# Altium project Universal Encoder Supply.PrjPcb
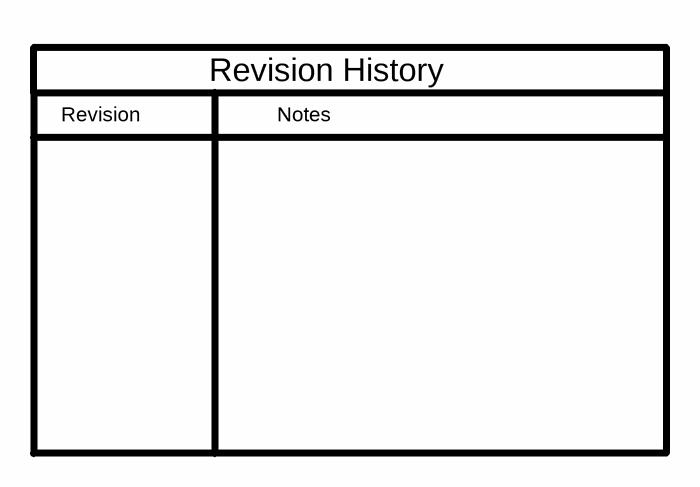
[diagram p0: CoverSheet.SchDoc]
CopyrightYear: 2015; EVM_Orderable: N/A; PCB_Layout: V.Pizzolante; PCB_Rev: E1; PRJ_Customer: Public Release; PRJ_Engineer: V.Pizzolante; PRJ_Number: TIDA-00179; PRJ_Title: Universal Digital Interface to Absolute Encoders; SCH_Rev: E1; TechSupport: http://www.ti.com/support; TID: TIDA-00179
6 sheets, 194 parts. Net scope: global (net labels, ports and power ports of the same name join across sheets).
Board file: TID.PcbDoc
Sheets:
  CoverSheet.SchDoc
  Power.SchDoc
  Protections.SchDoc
  Host_Interface_MUX.SchDoc
  RS485.SchDoc
  TID_Hardware.SchDoc

## Sheet CoverSheet.SchDoc
size 431 x 279 mm; Date: Not shown in title block; ApprovedBy: Not shown in title block; CheckedBy: Not shown in title block; Author: Not shown in title block; CompanyName: Not shown in title block; Engineer: Not shown in title block; Organization: Not shown in title block; Address1: Not shown in title block; Address2: Not shown in title block; Address3: Not shown in title block; Address4: Not shown in title block; DocumentNumber: 1; Revision: Use project parameter SCH_Rev; SheetNumber: 1; SheetTotal: 3; PageSetup: Record=PageOptions¦CenterHorizontal=True¦CenterVertical=True¦PrintScale=0.64¦XCorrection=1.00¦YCorrection=1.00¦PrintKind=0¦BorderSize=5000000¦LeftOffset=0¦BottomOffset=0¦Orientation=2¦PaperLength=1000¦PaperWidth=1000¦Scale=100¦PaperSource=15¦PrintQuality=600¦MediaType=1¦DitherType=10¦PrintScaleMode=1¦PaperKind=Letter

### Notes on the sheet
- Revision
- Notes
- Revision History

## Sheet Power.SchDoc
size 431 x 279 mm; Date: Not shown in title block; ApprovedBy: Not shown in title block; CheckedBy: Not shown in title block; Author: Not shown in title block; CompanyName: Not shown in title block; Engineer: Not shown in title block; Organization: Not shown in title block; Address1: Not shown in title block; Address2: Not shown in title block; Address3: Not shown in title block; Address4: Not shown in title block; DocumentNumber: 1; Revision: Use project parameter SCH_Rev; SheetNumber: 2; SheetTotal: 3
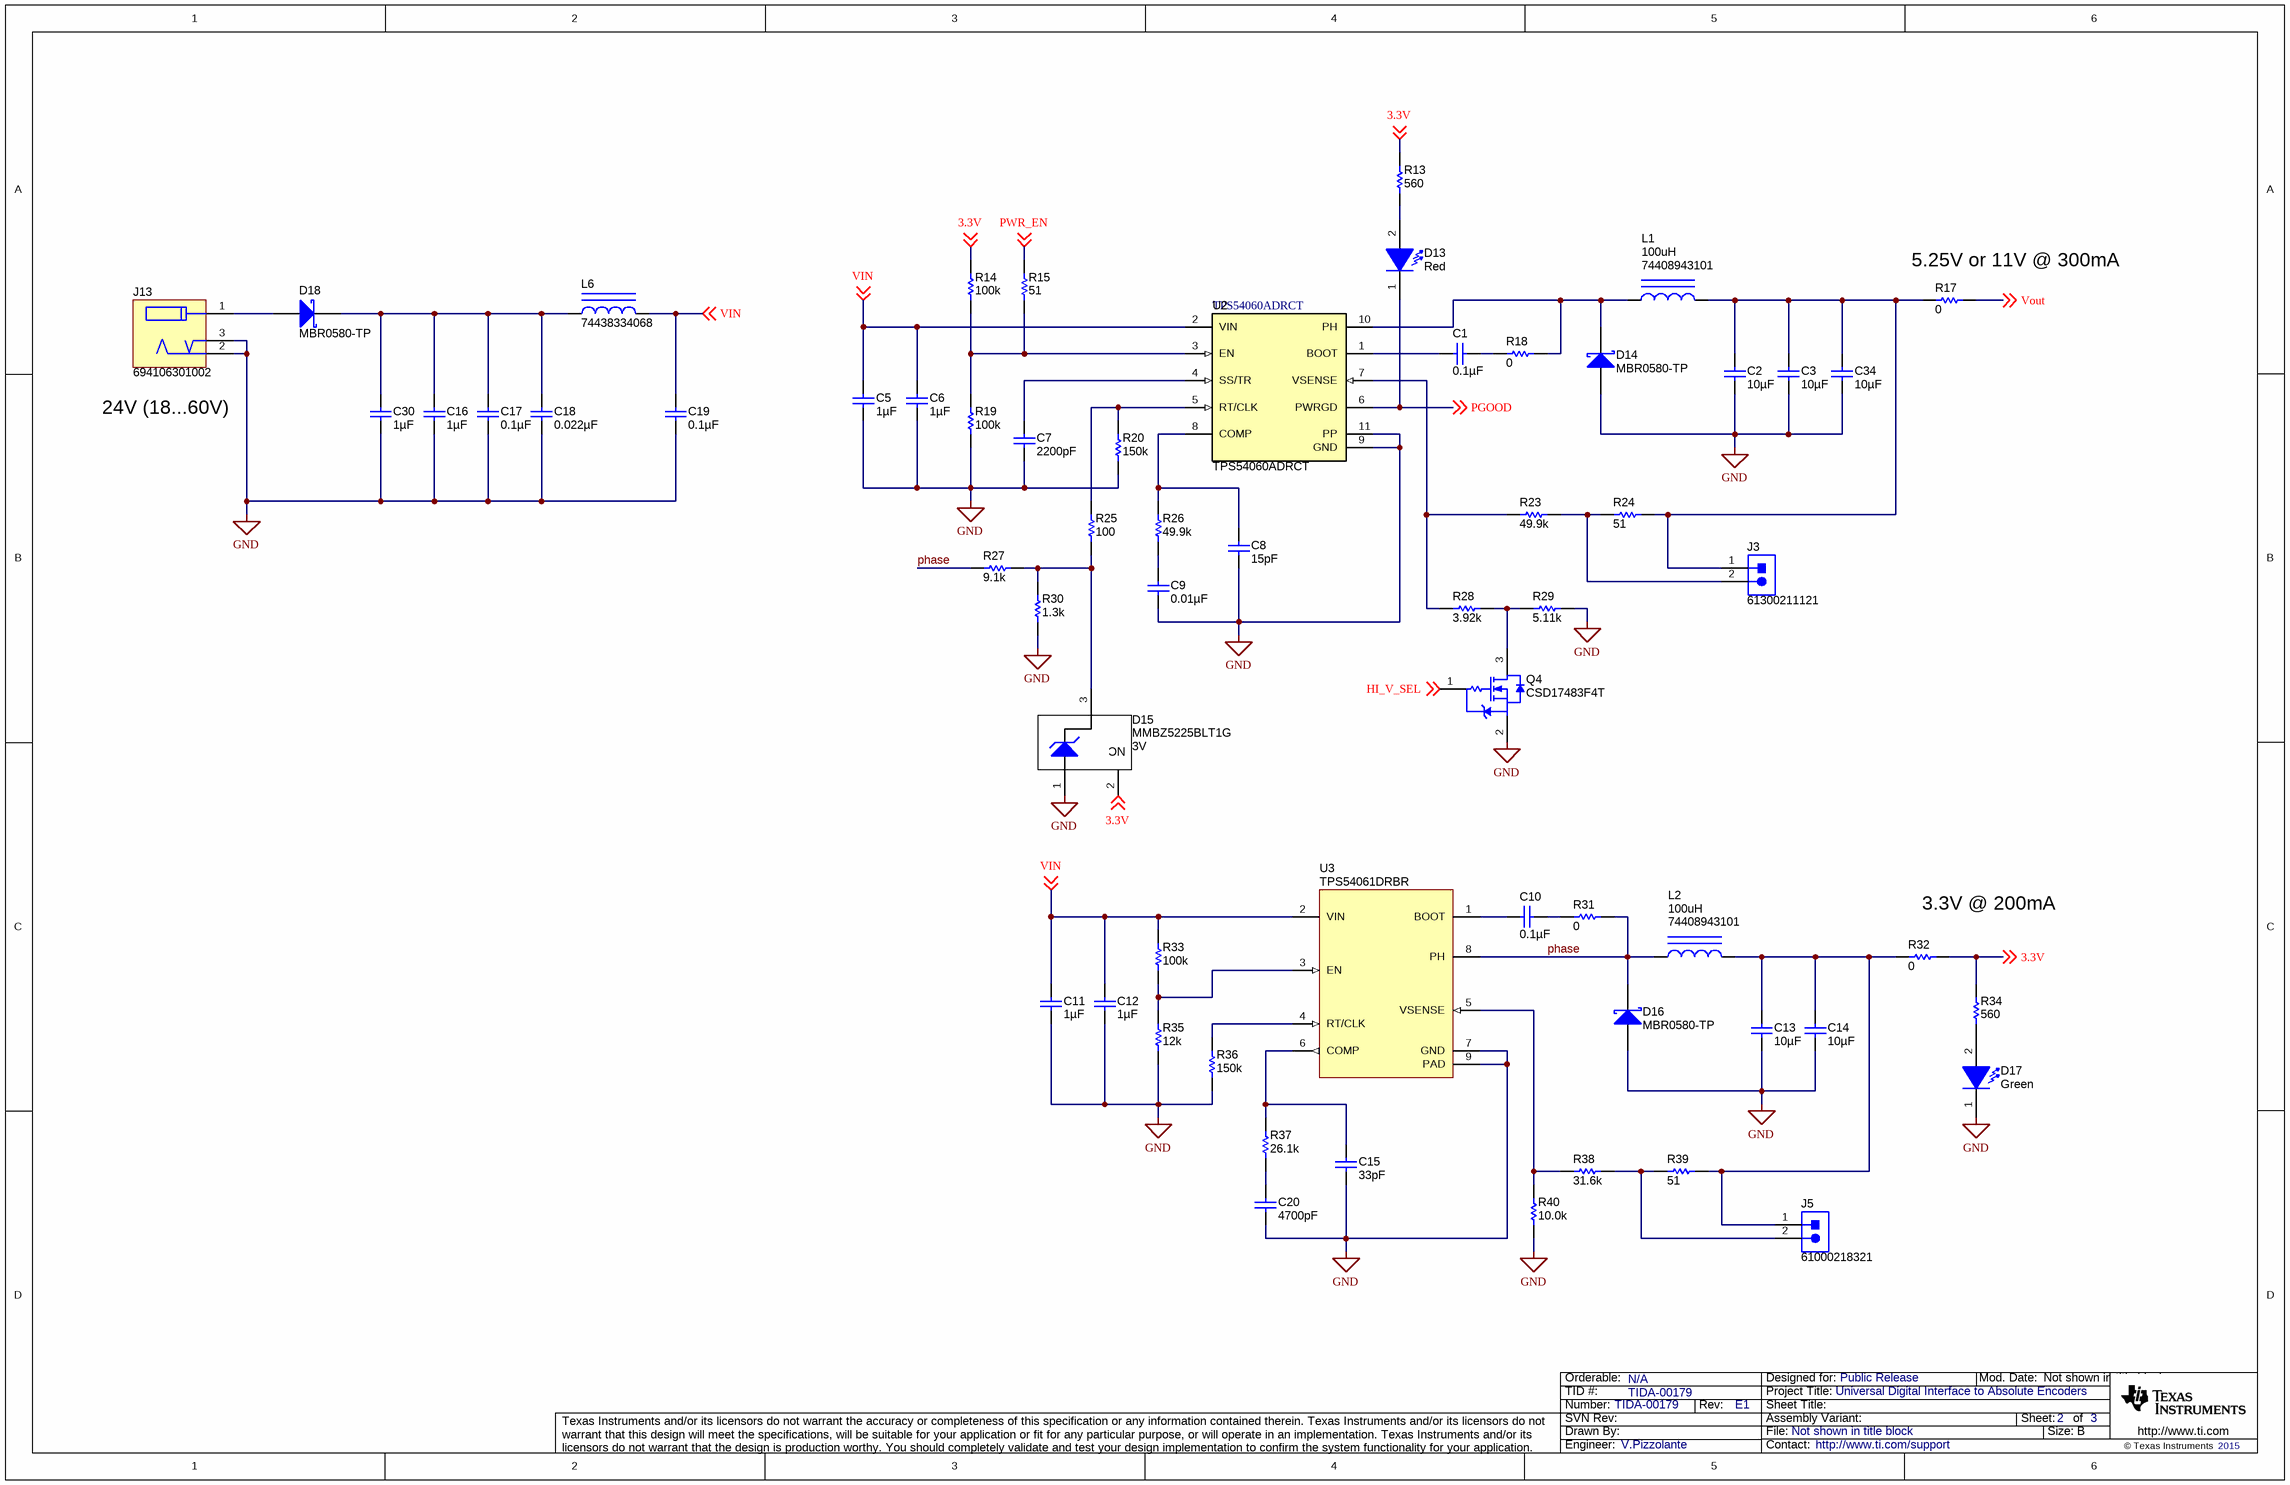
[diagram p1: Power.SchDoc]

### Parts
C1  ValueDisplayed: 0.1µF  [0603]  (hidden comment: GRM188R72A104KA35D)
C2  ValueDisplayed: 10µF  [0805_HV]  (hidden comment: C2012X5R1E106K125AB)
C3  ValueDisplayed: 10µF  [0805_HV]  (hidden comment: C2012X5R1E106K125AB)
C5  ValueDisplayed: 1µF  [0805_145]  (hidden comment: C2012X7S2A105K125AB)
C6  ValueDisplayed: 1µF  [0805_145]  (hidden comment: C2012X7S2A105K125AB)
C7  ValueDisplayed: 2200pF  [0603_095]  (hidden comment: 885012206036)
C8  ValueDisplayed: 15pF  [0402]  (hidden comment: 885012005056)
C9  ValueDisplayed: 0.01µF  [0402]  (hidden comment: 885012205031)
C10  ValueDisplayed: 0.1µF  [0603]  (hidden comment: GRM188R72A104KA35D)
C11  ValueDisplayed: 1µF  [0805_145]  (hidden comment: C2012X7S2A105K125AB)
C12  ValueDisplayed: 1µF  [0805_145]  (hidden comment: C2012X7S2A105K125AB)
C13  ValueDisplayed: 10µF  [0805_HV]  (hidden comment: C2012X5R1E106K125AB)
C14  ValueDisplayed: 10µF  [0805_HV]  (hidden comment: C2012X5R1E106K125AB)
C15  ValueDisplayed: 33pF  [0402]  (hidden comment: 885012005043)
C16  ValueDisplayed: 1µF  [0805_145]  (hidden comment: C2012X7S2A105K125AB)
C17  ValueDisplayed: 0.1µF  [0805_HV]  (hidden comment: C0805C104K1RACTU)
C18  ValueDisplayed: 0.022µF  [0603]  (hidden comment: C1608X7R2A223K)
C19  ValueDisplayed: 0.1µF  [0805_HV]  (hidden comment: C0805C104K1RACTU)
C20  ValueDisplayed: 4700pF  [0402]  (hidden comment: GRM155R71E472KA01D)
C30  ValueDisplayed: 1µF  [0805_145]  (hidden comment: C2012X7S2A105K125AB)
C34  ValueDisplayed: 10µF  [0805_HV]  (hidden comment: C2012X5R1E106K125AB)
D13  value Red  [WL-SMCW_RED]  (hidden comment: 150060RS75000)
D14  MBR0580-TP  [SOD-123]
D15  MMBZ5225BLT1G  value 3V  [SOT-23]
D16  MBR0580-TP  [SOD-123]
D17  value Green  [WL-SMCW_GREEN]  (hidden comment: 150060GS75000)
D18  MBR0580-TP  [SOD-123]
J3  61300211121  [WURTH_61300211121]
J5  61000218321  [Wurth_61000218321]
J13  694106301002  [Wurth_694106301002]
L1  74408943101  value 100uH  [WE-SPC_4838]
L2  74408943101  value 100uH  [WE-SPC_4838]
L6  74438334068  [WE-MAPI_3012]
Q4  CSD17483F4T  [YJC0003A]
R13  ValueDisplayed: 560  [0402]  (hidden comment: CRCW0402560RJNED)
R14  ValueDisplayed: 100k  [0402]  (hidden comment: CRCW0402100KJNED)
R15  ValueDisplayed: 51  [0402]  (hidden comment: CRCW040251R0JNED)
R17  value 0  [0603]  (hidden comment: CRCW06030000Z0EA)
R18  ValueDisplayed: 0  [0402]  (hidden comment: CRCW04020000Z0ED)
R19  ValueDisplayed: 100k  [0402]  (hidden comment: CRCW0402100KJNED)
R20  ValueDisplayed: 150k  [0402]  (hidden comment: CRCW0402150KJNED)
R23  ValueDisplayed: 49.9k  [0402]  (hidden comment: CRCW040249K9FKED)
R24  ValueDisplayed: 51  [0402]  (hidden comment: CRCW040251R0JNED)
R25  ValueDisplayed: 100  [0402]  (hidden comment: CRCW0402100RJNED)
R26  ValueDisplayed: 49.9k  [0402]  (hidden comment: CRCW040249K9FKED)
R27  ValueDisplayed: 9.1k  [0402]  (hidden comment: CRCW04029K10JNED)
R28  ValueDisplayed: 3.92k  [0402]  (hidden comment: CRCW04023K92FKED)
R29  ValueDisplayed: 5.11k  [0402]  (hidden comment: CRCW04025K11FKED)
R30  ValueDisplayed: 1.3k  [0402]  (hidden comment: CRCW04021K30JNED)
R31  ValueDisplayed: 0  [0402]  (hidden comment: CRCW04020000Z0ED)
R32  value 0  [0603]  (hidden comment: CRCW06030000Z0EA)
R33  ValueDisplayed: 100k  [0402]  (hidden comment: CRCW0402100KJNED)
R34  ValueDisplayed: 560  [0402]  (hidden comment: CRCW0402560RJNED)
R35  ValueDisplayed: 12k  [0402]  (hidden comment: CRCW040212K0JNED)
R36  ValueDisplayed: 150k  [0402]  (hidden comment: CRCW0402150KJNED)
R37  ValueDisplayed: 26.1k  [0402]  (hidden comment: CRCW040226K1FKED)
R38  ValueDisplayed: 31.6k  [0402]  (hidden comment: CRCW040231K6FKED)
R39  ValueDisplayed: 51  [0402]  (hidden comment: CRCW040251R0JNED)
R40  ValueDisplayed: 10.0k  [0402]  (hidden comment: CRCW040210K0FKED)
U2  TPS54060ADRCT  [DRC0010J]
U3  TPS54061DRBR  [DRB0008B]

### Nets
GND: C2.2 C3.2 C5.2 C6.2 C7.2 C8.2 C9.2 C11.2 C12.2 C13.2 C14.2 C15.2 C16.2 C17.2 C18.2 C19.2 C20.2 C30.2 C34.2 D14.2(A) D15.1(A) D16.2(A) D17.1(K) J13.2 J13.3 Q4.2(S) R19.1 R20.1 R29.2 R30.1 R35.1 R36.1 R40.1 U2.9(GND) U2.11(PP) U3.7(GND) U3.9(PAD)
3.3V: D15.2(NC) R13.2 R14.2 R32.2 R34.2 ; off-sheet 3.3V
HI_V_SEL: Q4.1(G) ; off-sheet HI_V_SEL
PGOOD: D13.1(K) U2.6(PWRGD) ; off-sheet PGOOD
phase: D16.1(K) L2.1 R27.1 R31.2 U3.8(PH)
PWR_EN: R15.2 ; off-sheet PWR_EN
VIN: C5.1 C6.1 C11.1 C12.1 C19.1 L6.2 R33.1 U2.2(VIN) U3.2(VIN) ; off-sheet VIN
Vout: R17.2 ; off-sheet Vout
NetC1_1: C1.1 R18.1
NetC1_2: C1.2 U2.1(BOOT)
NetC2_1: C2.1 C3.1 C34.1 J3.1 L1.2 R17.1 R24.2
NetC7_1: C7.1 U2.4(SS/TR)
NetC8_1: C8.1 R26.2 U2.8(COMP)
NetC9_1: C9.1 R26.1
NetC10_1: C10.1 R31.1
NetC10_2: C10.2 U3.1(BOOT)
NetC13_1: C13.1 C14.1 J5.1 L2.2 R32.1 R39.2
NetC15_1: C15.1 R37.2 U3.6(COMP)
NetC16_1: C16.1 C17.1 C18.1 C30.1 D18.1(K) L6.1
NetC20_1: C20.1 R37.1
NetD13_2: D13.2(A) R13.1
NetD14_1: D14.1(K) L1.1 R18.2 U2.10(PH)
NetD15_3: D15.3(K) R25.1 R27.2 R30.2
NetD17_2: D17.2(A) R34.1
NetD18_2: D18.2(A) J13.1
NetJ3_2: J3.2 R23.1 R24.1
NetJ5_2: J5.2 R38.2 R39.1
NetQ4_3: Q4.3(D) R28.2 R29.1
NetR14_1: R14.1 R15.1 R19.2 U2.3(EN)
NetR20_2: R20.2 R25.2 U2.5(RT/CLK)
NetR23_2: R23.2 R28.1 U2.7(VSENSE)
NetR33_2: R33.2 R35.2 U3.3(EN)
NetR36_2: R36.2 U3.4(RT/CLK)
NetR38_1: R38.1 R40.2 U3.5(VSENSE)

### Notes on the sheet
- (near R17) 5.25V or 11V @ 300mA
- (near J13) 24V (18...60V)
- (near R32) 3.3V @ 200mA

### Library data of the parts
C1 C10 = GRM188R72A104KA35D: CAP, CERM, 0.1 µF, 100 V, +/- 10%, X7R, 0603; Manufacturer: MuRata; Polarized: N; CompType: Capacitor; Value: 0.1uF; U/M: EA; Cap_F: 0.0000001; Tolerance_%: 10; Value1: Unknown; VDC_V: 100; Value2: 100V; TaMin_C: -55; TaMax_C: 125
C2 C3 C13 C14 C34 = C2012X5R1E106K125AB: CAP, CERM, 10uF, 25V, +/-10%, X5R, 0805; Manufacturer: TDK; Polarized: N; CompType: Capacitor; U/M: EA; Cap_F: 0.00001; Tolerance_%: 10; Value1: Unknown; VDC_V: 25; TaMin_C: -55; TaMax_C: 85; Cap_Case: 0805
C5 C6 C11 C12 C16 C30 = C2012X7S2A105K125AB: CAP, CERM, 1 µF, 100 V, +/- 10%, X7S, 0805; Manufacturer: TDK; Polarized: N; CompType: Capacitor; Value: 1uF; U/M: EA; Cap_F: 0.000001; Tolerance_%: 10; Value1: Unknown; VDC_V: 100; Value2: 100V; TaMin_C: -55; TaMax_C: 125; Cap_Case: 0805
C7 = 885012206036: CAP, CERM, 2200 pF, 16 V, +/- 10%, X7R, 0603_095; Manufacturer: Wurth Elektronik; Polarized: N; CompType: Capacitor; Value: 2200pF; U/M: EA; Cap_F: 0.0000000022; Tolerance_%: 10; Value1: Unknown; VDC_V: 16; Value2: 16V; TaMin_C: -55; TaMax_C: 125; Cap_Case: 0603
C8 = 885012005056: CAP, CERM, 15 pF, 50 V, +/- 5%, C0G/NP0, 0402; Manufacturer: Wurth Elektronik; Polarized: N; CompType: Capacitor; Value: 15pF; U/M: EA; Cap_F: 0.000000000015; Tolerance_%: 5; Value1: Unknown; VDC_V: 50; Value2: 50V; TaMin_C: -55; TaMax_C: 125
C9 = 885012205031: CAP, CERM, 0.01 µF, 16 V, +/- 10%, X7R, 0402; Manufacturer: Wurth Elektronik; Polarized: N; CompType: Capacitor; Value: 0.01uF; U/M: EA; Cap_F: 0.00000001; Tolerance_%: 10; Value1: Unknown; VDC_V: 16; Value2: 16V; TaMin_C: -55; TaMax_C: 125
C15 = 885012005043: CAP, CERM, 33 pF, 25 V, +/- 5%, C0G/NP0, 0402; Manufacturer: Wurth Elektronik; Polarized: N; CompType: Capacitor; Value: 33pF; U/M: EA; Cap_F: 0.000000000033; Tolerance_%: 5; Value1: Unknown; VDC_V: 25; Value2: 25V; TaMin_C: -55; TaMax_C: 125
C17 C19 = C0805C104K1RACTU: CAP, CERM, 0.1 µF, 100 V, +/- 10%, X7R, 0805; Manufacturer: Kemet; Polarized: N; CompType: Capacitor; Value: 0.1uF; U/M: EA; Cap_F: 0.0000001; Tolerance_%: 10; ESR_ohm: 0.064; Value1: 0.064 ohm; VDC_V: 100; Value2: 100V; IRMS_A: 1.64; TaMin_C: -55; TaMax_C: 125; Cap_Case: 0805
C18 = C1608X7R2A223K: CAP, CERM, 0.022 µF, 100 V, +/- 10%, X7R, 0603; Manufacturer: TDK; Polarized: N; CompType: Capacitor; Value: 0.022uF; U/M: EA; Cap_F: 0.000000022; Tolerance_%: 10; ESR_ohm: 0.037; Value1: 0.037 ohm; VDC_V: 100; Value2: 100V; TaMin_C: -55; TaMax_C: 125
C20 = GRM155R71E472KA01D: CAP, CERM, 4700 pF, 25 V, +/- 10%, X7R, 0402; Manufacturer: MuRata; Polarized: N; CompType: Capacitor; Value: 4700pF; U/M: EA; Cap_F: 0.0000000047; Tolerance_%: 10; Value1: Unknown; VDC_V: 25; Value2: 25V; TaMin_C: -55; TaMax_C: 125
D13 = 150060RS75000: LED, Red, SMD; Manufacturer: Wurth Elektronik; Type: AlInGaP; Vf_V: 2; Value2: 2V; Io_A: 0.03; Vr_V: 5; Tjmax_C: 85; Power_TotalModule: 0.072; Value1: 0.072W; Angle: 140; U/M: EA
D14 D16 D18 = MBR0580-TP: Diode, Schottky, 80 V, 0.5 A, SOD-123; Manufacturer: Micro Commercial Components; U/M: EA; Vf_V: 0.8; Value: 80V; Value1: 0.5A; Value2: 0.8V; Io_A: 0.5; Vr_V: 80; TJmax_C: 150
D15 = MMBZ5225BLT1G: Diode, Zener, 3 V, 225 mW, SOT-23; Manufacturer: ON Semiconductor; U/M: EA; Power_W: 0.225; Vz_V: 3; Value1: 0.225W; RJA_CperW: 556
D17 = 150060GS75000: LED, Green, SMD; Manufacturer: Wurth Elektronik; Type: InGaN; Vf_V: 3.2; Value2: 3.2V; Io_A: 0.02; Tjmax_C: 85; Value1: W; Angle: 140; U/M: EA
J3 = 61300211121: Header, 2.54 mm, 2x1, Gold, TH; Manufacturer: Wurth Elektronik; SymbolCreator: a0412235; U/M: EA
J5 = 61000218321: Header, 2.54mm, 2x1, Gold, SMT; Manufacturer: Wurth Elektronik; SymbolCreator: a0412235; U/M: EA
J13 = 694106301002: WR-DC DC Power Jack, R/A, TH; Manufacturer: Wurth Elektronik; SymbolCreator: a0799628; U/M: EA
L1 L2 = 74408943101: Inductor, Shielded Drum Core, Ferrite, 100 µH, 0.52 A, 0.77 ohm, SMD; Manufacturer: Wurth Elektronik; Ind_H: 100.0E-6; ValueDisplayed: 100µH; Imax_A: 0.52; Irms: 0.52A @ 40C rise; Isat: 0.68A @ 35% inductance drop; DCR_ohm: 0.77; Value2: 0.52A
L6 = 74438334068: Inductor, Shielded, 6.8 µH, 0.88 A, 0.3682 ohm, SMD; Manufacturer: Wurth Elektronik; Value: 6.8uH; Ind_H: 6.8E-6; ValueDisplayed: 6.8µH; Imax_A: 0.88; Irms: 0.88A @ 40C rise; Isat: 2.7A @ 20% inductance drop; DCR_ohm: 0.3682; Value2: 0.88A
Q4 = CSD17483F4T: MOSFET, N/P-CH, 30 V, 1.5 A,; Manufacturer: Texas Instruments; Alternate Manufacturer: None; U/M: EA; ChType: N; Value: 30V; VdsMax_V: 30; Value1: 0.2 ohm; Rdson45_ohm: 0.2; Value2: 1.01 nC; QgTyp_nC: 1.01; Vgs_V: 12; IdsMax_A: 1.5; SymbolCreator: a0411947
R13 R34 = CRCW0402560RJNED: RES, 560, 5%, 0.063 W, 0402; Manufacturer: Vishay-Dale; CompType: Resistor; Value: 560; Value_Code: 560R; Tolerance_%: 5; Power_W: 0.063; Value2: 0.063W; VDC_V: 50; TempCo: 200 ppm/C; EIA_Code: E24; U/M: EA
R14 R19 R33 = CRCW0402100KJNED: RES, 100 k, 5%, 0.063 W, 0402; Manufacturer: Vishay-Dale; CompType: Resistor; Value: 100k; Res_ohm: 100000; Tolerance_%: 5; Power_W: 0.063; Value2: 0.063W; VDC_V: 50; TempCo: 200 ppm/C; EIA_Code: E24; U/M: EA
R15 R24 R39 = CRCW040251R0JNED: RES, 51, 5%, 0.063 W, 0402; Manufacturer: Vishay-Dale; CompType: Resistor; Value: 51; Value_Code: 51R0; Tolerance_%: 5; Power_W: 0.063; Value2: 0.063W; VDC_V: 50; TempCo: 200 ppm/C; EIA_Code: E24; U/M: EA
R17 R32 = CRCW06030000Z0EA: RES, 0 ohm, 5%, 0.1W, 0603; Manufacturer: Vishay-Dale; CompType: Resistor; Value_Code: 0000; Tolerance_%: 5; Power_W: 0.1; VDC_V: 75; TempCo: 200 ppm/C; EIA_Code: E24; U/M: EA
R18 R31 = CRCW04020000Z0ED: RES, 0, 5%, 0.063 W, 0402; Manufacturer: Vishay-Dale; CompType: Resistor; Value: 0; Value_Code: 0000; Tolerance_%: 5; Power_W: 0.063; Value2: 0.063W; VDC_V: 50; TempCo: 200 ppm/C; EIA_Code: E24; U/M: EA
R20 R36 = CRCW0402150KJNED: RES, 150 k, 5%, 0.063 W, 0402; Manufacturer: Vishay-Dale; CompType: Resistor; Value: 150k; Res_ohm: 150000; Tolerance_%: 5; Power_W: 0.063; Value2: 0.063W; VDC_V: 50; TempCo: 200 ppm/C; EIA_Code: E24; U/M: EA
R23 R26 = CRCW040249K9FKED: RES, 49.9 k, 1%, 0.063 W, 0402; Manufacturer: Vishay-Dale; CompType: Resistor; Value: 49.9k; Res_ohm: 49900; Value_Code: 49k9; Tolerance_%: 1; Power_W: 0.063; Value2: 0.063W; VDC_V: 50; TempCo: 100 ppm/C; EIA_Code: E96; U/M: EA
R25 = CRCW0402100RJNED: RES, 100, 5%, 0.063 W, 0402; Manufacturer: Vishay-Dale; CompType: Resistor; Value: 100; Value_Code: 100R; Tolerance_%: 5; Power_W: 0.063; Value2: 0.063W; VDC_V: 50; TempCo: 200 ppm/C; EIA_Code: E24; U/M: EA
R27 = CRCW04029K10JNED: RES, 9.1 k, 5%, 0.063 W, 0402; Manufacturer: Vishay-Dale; CompType: Resistor; Value: 9.1k; Res_ohm: 9100; Value_Code: 9k10; Tolerance_%: 5; Power_W: 0.063; Value2: 0.063W; VDC_V: 50; TempCo: 200 ppm/C; EIA_Code: E24; U/M: EA
R28 = CRCW04023K92FKED: RES, 3.92 k, 1%, 0.063 W, 0402; Manufacturer: Vishay-Dale; CompType: Resistor; Value: 3.92k; Res_ohm: 3920; Value_Code: 3k92; Tolerance_%: 1; Power_W: 0.063; Value2: 0.063W; VDC_V: 50; TempCo: 100 ppm/C; EIA_Code: E96; U/M: EA
R29 = CRCW04025K11FKED: RES, 5.11 k, 1%, 0.063 W, 0402; Manufacturer: Vishay-Dale; CompType: Resistor; Value: 5.11k; Res_ohm: 5110; Value_Code: 5k11; Tolerance_%: 1; Power_W: 0.063; Value2: 0.063W; VDC_V: 50; TempCo: 100 ppm/C; EIA_Code: E96; U/M: EA
R30 = CRCW04021K30JNED: RES, 1.3 k, 5%, 0.063 W, 0402; Manufacturer: Vishay-Dale; CompType: Resistor; Value: 1.3k; Res_ohm: 1300; Value_Code: 1k30; Tolerance_%: 5; Power_W: 0.063; Value2: 0.063W; VDC_V: 50; TempCo: 200 ppm/C; EIA_Code: E24; U/M: EA
R35 = CRCW040212K0JNED: RES, 12 k, 5%, 0.063 W, 0402; Manufacturer: Vishay-Dale; CompType: Resistor; Value: 12k; Res_ohm: 12000; Value_Code: 12k0; Tolerance_%: 5; Power_W: 0.063; Value2: 0.063W; VDC_V: 50; TempCo: 200 ppm/C; EIA_Code: E24; U/M: EA
R37 = CRCW040226K1FKED: RES, 26.1 k, 1%, 0.063 W, 0402; Manufacturer: Vishay-Dale; CompType: Resistor; Value: 26.1k; Res_ohm: 26100; Value_Code: 26k1; Tolerance_%: 1; Power_W: 0.063; Value2: 0.063W; VDC_V: 50; TempCo: 100 ppm/C; EIA_Code: E96; U/M: EA
R38 = CRCW040231K6FKED: RES, 31.6 k, 1%, 0.063 W, 0402; Manufacturer: Vishay-Dale; CompType: Resistor; Value: 31.6k; Res_ohm: 31600; Value_Code: 31k6; Tolerance_%: 1; Power_W: 0.063; Value2: 0.063W; VDC_V: 50; TempCo: 100 ppm/C; EIA_Code: E96; U/M: EA
R40 = CRCW040210K0FKED: RES, 10.0 k, 1%, 0.063 W, 0402; Manufacturer: Vishay-Dale; CompType: Resistor; Value: 10.0k; Res_ohm: 10000; Value_Code: 10k0; Tolerance_%: 1; Power_W: 0.063; Value2: 0.063W; VDC_V: 50; TempCo: 100 ppm/C; EIA_Code: E96; U/M: EA
U2 = TPS54060DRCT: Buck Inverting Buck-Boost Step Down Regulator with 3.5 to 60 V Input and 0.8 to 58 V Output, -40 to 150 degC, 10-Pin SON (DRC), Green (RoHS & no Sb/Br); Manufacturer: Texas Instruments; Alternate PartNumber: Equivalent; Duty Cycle(Max)(%): 98; Iout(Max)(A): 0.5; Iq(Typ)(mA): 0.116; Rating: Catalog; Regulated Outputs(#): 1; SubFamily: Step-Down Regulator; Switch Current Limit(Typ)(A): 0.6; Topology: Buck, Inverting Buck-Boost; Vin(Max)(V): 60; Vin(Min)(V): 3.5; Vout(Max)(V): 58; Vout(Min)(V): 0.8
U3 = TPS54061DRBR: Wide Input 60-V, 200-mA Synchronous Step-Down DC-DC Converter With Low IQ, DRB0008B; Alternate PartNumber: TPS54061DRBT; Manufacturer: Texas Instruments; SymbolCreator: a0411947; CompType: IC; U/M: EA

## Sheet Protections.SchDoc
size 431 x 279 mm; Date: Not shown in title block; ApprovedBy: Not shown in title block; CheckedBy: Not shown in title block; Author: Not shown in title block; CompanyName: Not shown in title block; Engineer: Not shown in title block; Organization: Not shown in title block; Address1: Not shown in title block; Address2: Not shown in title block; Address3: Not shown in title block; Address4: Not shown in title block; DocumentNumber: 1; Revision: Use project parameter SCH_Rev; SheetNumber: 2; SheetTotal: 3
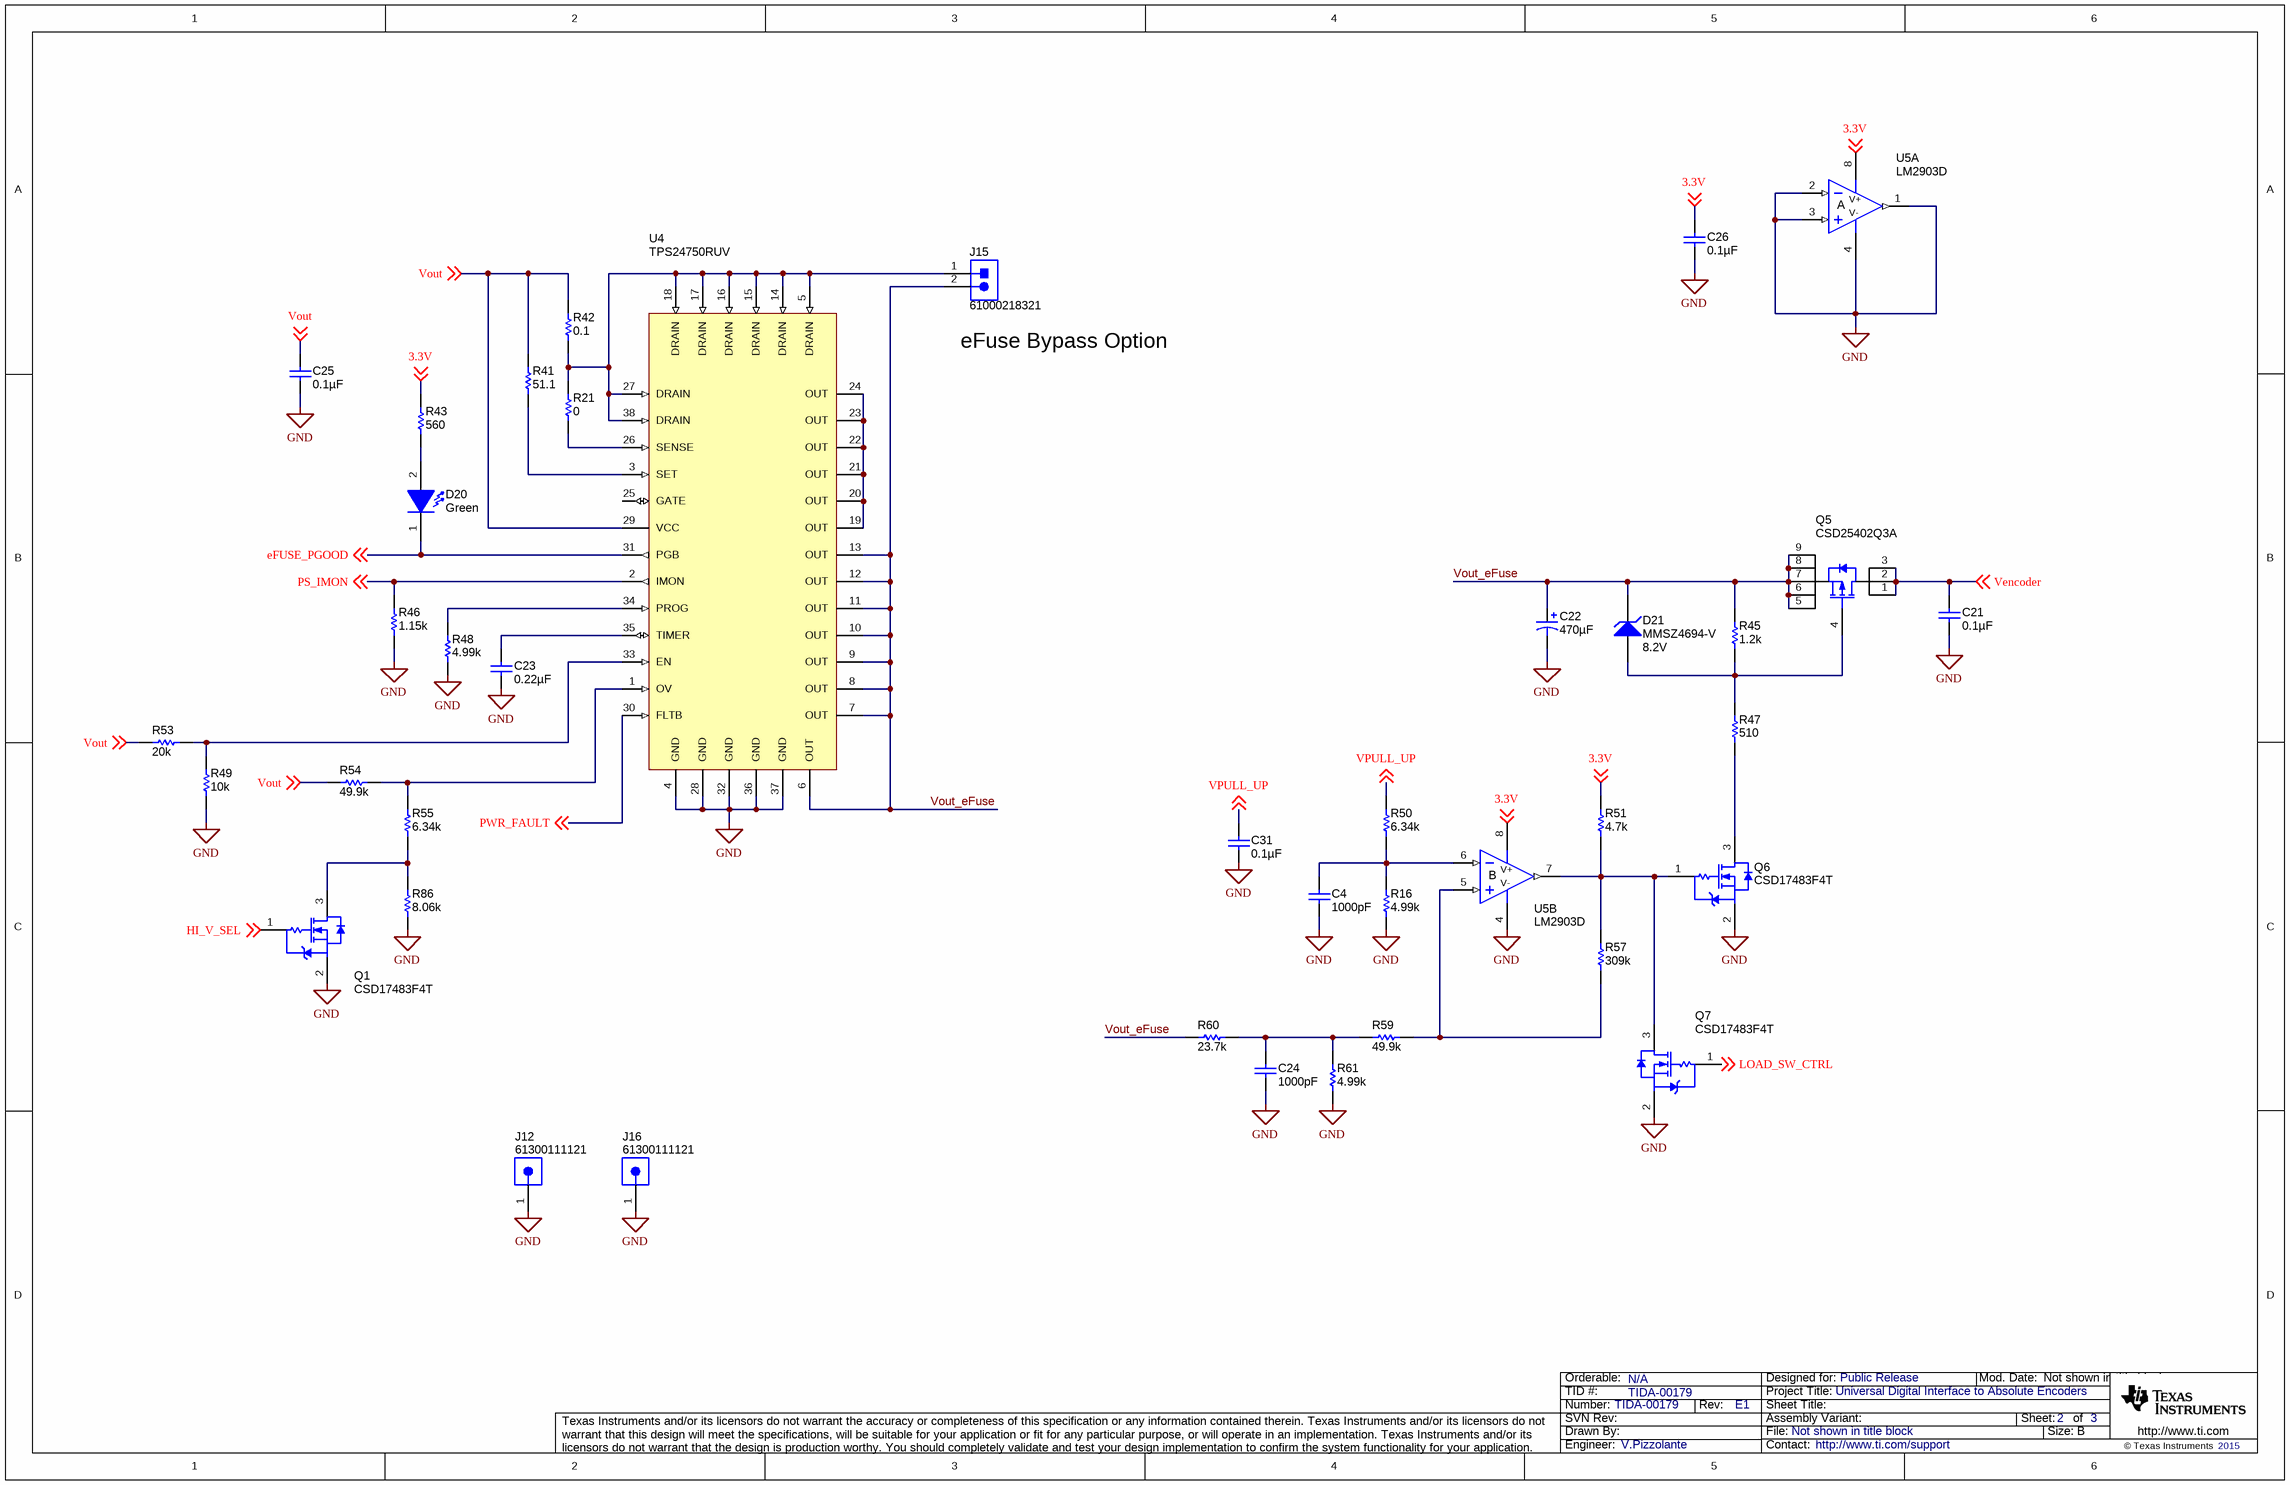
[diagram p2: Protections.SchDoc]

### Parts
C4  ValueDisplayed: 1000pF  [0402]  (hidden comment: 885012205044)
C21  ValueDisplayed: 0.1µF  [0603_095]  (hidden comment: 885012206071)
C22  ValueDisplayed: 470µF  [WCAP_ASLI_1000x1050]  (hidden comment: 865080457015)
C23  ValueDisplayed: 0.22µF  [0603_095]  (hidden comment: 885012206048)
C24  ValueDisplayed: 1000pF  [0402]  (hidden comment: 885012205044)
C25  ValueDisplayed: 0.1µF  [0603_095]  (hidden comment: 885012206046)
C26  ValueDisplayed: 0.1µF  [0603_095]  (hidden comment: 885012206046)
C31  ValueDisplayed: 0.1µF  [0603_095]  (hidden comment: 885012206046)
D20  value Green  [WL-SMCW_GREEN]  (hidden comment: 150060GS75000)
D21  MMSZ4694-V  value 8.2V  [SOD-123]
J12  61300111121  [WURTH_61300111121]
J15  61000218321  [Wurth_61000218321]
J16  61300111121  [WURTH_61300111121]
Q1  CSD17483F4T  [YJC0003A]
Q5  CSD25402Q3A  [TRANS_NexFET_Q3A]
Q6  CSD17483F4T  [YJC0003A]
Q7  CSD17483F4T  [YJC0003A]
R16  ValueDisplayed: 4.99k  [0402]  (hidden comment: CRCW04024K99FKED)
R21  ValueDisplayed: 0  [0402]  (hidden comment: CRCW04020000Z0ED)
R41  ValueDisplayed: 51.1  [0402]  (hidden comment: CRCW040251R1FKED)
R42  ValueDisplayed: 0.1  [0805_HV]  (hidden comment: ERJ-6RSFR10V)
R43  ValueDisplayed: 560  [0402]  (hidden comment: CRCW0402560RJNED)
R45  ValueDisplayed: 1.2k  [0402]  (hidden comment: CRCW04021K20JNED)
R46  ValueDisplayed: 1.15k  [0402]  (hidden comment: CRCW04021K15FKED)
R47  ValueDisplayed: 510  [0402]  (hidden comment: CRCW0402510RJNED)
R48  ValueDisplayed: 4.99k  [0402]  (hidden comment: CRCW04024K99FKED)
R49  ValueDisplayed: 10k  [0402]  (hidden comment: CRCW040210K0JNED)
R50  ValueDisplayed: 6.34k  [0402]  (hidden comment: CRCW04026K34FKED)
R51  ValueDisplayed: 4.7k  [0402]  (hidden comment: CRCW04024K70JNED)
R53  ValueDisplayed: 20k  [0402]  (hidden comment: CRCW040220K0JNED)
R54  ValueDisplayed: 49.9k  [0402]  (hidden comment: CRCW040249K9FKED)
R55  ValueDisplayed: 6.34k  [0402]  (hidden comment: CRCW04026K34FKED)
R57  ValueDisplayed: 309k  [0402]  (hidden comment: CRCW0402309KFKED)
R59  ValueDisplayed: 49.9k  [0402]  (hidden comment: CRCW040249K9FKED)
R60  ValueDisplayed: 23.7k  [0402]  (hidden comment: CRCW040223K7FKED)
R61  ValueDisplayed: 4.99k  [0402]  (hidden comment: CRCW04024K99FKED)
R86  ValueDisplayed: 8.06k  [0402]  (hidden comment: CRCW04028K06FKED)
U4  TPS24750RUV  [RUV0036A]
U5  LM2903D  [D0008A_N]  (parts A,B of 2)

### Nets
GND: C4.2 C21.2 C22.2(-) C23.2 C24.2 C25.1 C26.1 C31.1 J12.1 J16.1 Q1.2(S) Q6.2(S) Q7.2(S) R16.1 R46.1 R48.1 R49.1 R61.1 R86.1 U4.4(GND) U4.28(GND) U4.32(GND) U4.36(GND) U4.37(GND) U5.1(OUT) U5.2(IN-) U5.3(IN+) U5.4(V-)
3.3V: C26.2 R43.2 R51.2 U5.8(V+) ; off-sheet 3.3V
eFUSE_PGOOD: D20.1(K) U4.31(PGB) ; off-sheet eFUSE_PGOOD
HI_V_SEL: Q1.1(G) ; off-sheet HI_V_SEL
LOAD_SW_CTRL: Q7.1(G) ; off-sheet LOAD_SW_CTRL
PS_IMON: R46.2 U4.2(IMON) ; off-sheet PS_IMON
PWR_FAULT: U4.30(FLTB) ; off-sheet PWR_FAULT
Vencoder: C21.1 Q5.1(D) Q5.2(D) Q5.3(D) ; off-sheet Vencoder
Vout: C25.2 R41.2 R42.2 R53.1 R54.1 U4.29(VCC) ; off-sheet Vout
Vout_eFuse: C22.1(+) D21.1(K) J15.2 Q5.5(S) Q5.6(S) Q5.7(S) Q5.8(S) Q5.9(S) R45.2 R60.2 U4.6(OUT) U4.7(OUT) U4.8(OUT) U4.9(OUT) U4.10(OUT) U4.11(OUT) U4.12(OUT) U4.13(OUT)
VPULL_UP: C31.2 R50.2 ; off-sheet VPULL_UP
NetC4_1: C4.1 R16.2 R50.1 U5.6(IN-)
NetC23_1: C23.1 U4.35(TIMER)
NetC24_1: C24.1 R59.1 R60.1 R61.2
NetD20_2: D20.2(A) R43.1
NetD21_2: D21.2(A) Q5.4(G) R45.1 R47.2
NetJ15_1: J15.1 R21.2 R42.1 U4.5(DRAIN) U4.14(DRAIN) U4.15(DRAIN) U4.16(DRAIN) U4.17(DRAIN) U4.18(DRAIN) U4.27(DRAIN) U4.38(DRAIN)
NetQ1_3: Q1.3(D) R55.1 R86.2
NetQ6_1: Q6.1(G) Q7.3(D) R51.1 R57.2 U5.7(OUT)
NetQ6_3: Q6.3(D) R47.1
NetR21_1: R21.1 U4.26(SENSE)
NetR41_1: R41.1 U4.3(SET)
NetR48_2: R48.2 U4.34(PROG)
NetR49_2: R49.2 R53.2 U4.33(EN)
NetR54_2: R54.2 R55.2 U4.1(OV)
NetR57_1: R57.1 R59.2 U5.5(IN+)
NetU4_19: U4.19(OUT) U4.20(OUT) U4.21(OUT) U4.22(OUT) U4.23(OUT) U4.24(OUT)

Not connected (* = marked no-connect by the designer): U4 25(GATE)

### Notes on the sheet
- (near J15) eFuse Bypass Option

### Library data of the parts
C4 C24 = 885012205044: CAP, CERM, 1000 pF, 25 V, +/- 10%, X7R, 0402; Manufacturer: Wurth Elektronik; Polarized: N; CompType: Capacitor; Value: 1000pF; U/M: EA; Cap_F: 0.000000001; Tolerance_%: 10; Value1: Unknown; VDC_V: 25; Value2: 25V; TaMin_C: -55; TaMax_C: 125
C21 = 885012206071: CAP, CERM, 0.1 µF, 25 V, +/- 10%, X7R, 0603_095; Manufacturer: Wurth Elektronik; Polarized: N; CompType: Capacitor; Value: 0.1uF; U/M: EA; Cap_F: 0.0000001; Tolerance_%: 10; Value1: Unknown; VDC_V: 25; Value2: 25V; TaMin_C: -55; TaMax_C: 125; Cap_Case: 0603
C22 = 865080457015: CAP, AL, 470 µF, 25 V, +/- 20%, 0.15 ohm, SMD; Manufacturer: Wurth Elektronik; Polarized: Y; CompType: Capacitor; Value: 470uF; U/M: EA; Cap_F: 0.00047; Tolerance_%: 20; VDC_V: 25; Value2: 25V; ESR_ohm: 0.15; IRMS_A: 0.65; TaMin_C: -55; TaMax_C: 105; Cap_Case: 10x10.5mm
C23 = 885012206048: CAP, CERM, 0.22 µF, 16 V, +/- 10%, X7R, 0603_095; Manufacturer: Wurth Elektronik; Polarized: N; CompType: Capacitor; Value: 0.22uF; U/M: EA; Cap_F: 0.00000022; Tolerance_%: 10; Value1: Unknown; VDC_V: 16; Value2: 16V; TaMin_C: -55; TaMax_C: 125; Cap_Case: 0603
C25 C26 C31 = 885012206046: CAP, CERM, 0.1 µF, 16 V, +/- 10%, X7R, 0603_095; Manufacturer: Wurth Elektronik; Polarized: N; CompType: Capacitor; Value: 0.1uF; U/M: EA; Cap_F: 0.0000001; Tolerance_%: 10; Value1: Unknown; VDC_V: 16; Value2: 16V; TaMin_C: -55; TaMax_C: 125; Cap_Case: 0603
D20 = 150060GS75000: as D17 on sheet Power
D21 = MMSZ4694-V: Diode, Zener, 8.2 V, 500 mW, SOD-123; Manufacturer: Vishay-Semiconductor; SymbolCreator: a0412235; U/M: EA; Power_W: 0.5; Vz_V: 8.2; Value1: 0.5W; RJA_CperW: 67
J12 J16 = 61300111121: Header, 2.54 mm, 1x1, Gold, TH; Manufacturer: Wurth Elektronik; SymbolCreator: a0412235; U/M: EA
J15 = 61000218321: as J5 on sheet Power
Q1 Q6 Q7 = CSD17483F4T: as Q4 on sheet Power
Q5 = CSD25402Q3A: MOSFET, P-CH, -20 V, -15 A, SON 3.3x3.3mm; Manufacturer: Texas Instruments; Alternate Manufacturer: None; SymbolCreator: a0799628; U/M: EA; ChType: P; Value: -20V; Value1: 0.0077 ohm; Rdson45_ohm: 0.0077; Value2: 7.5 nC; QgTyp_nC: 7.5; Vgs_V: 12
R16 R48 R61 = CRCW04024K99FKED: RES, 4.99 k, 1%, 0.063 W, 0402; Manufacturer: Vishay-Dale; CompType: Resistor; Value: 4.99k; Res_ohm: 4990; Value_Code: 4k99; Tolerance_%: 1; Power_W: 0.063; Value2: 0.063W; VDC_V: 50; TempCo: 100 ppm/C; EIA_Code: E96; U/M: EA
R21 = CRCW04020000Z0ED: as R18 on sheet Power
R41 = CRCW040251R1FKED: RES, 51.1, 1%, 0.063 W, 0402; Manufacturer: Vishay-Dale; CompType: Resistor; Value: 51.1; Value_Code: 51R1; Tolerance_%: 1; Power_W: 0.063; Value2: 0.063W; VDC_V: 50; TempCo: 100 ppm/C; EIA_Code: E96; U/M: EA
R42 = ERJ-6RSFR10V: RES, 0.1, 1%, 0.125 W, 0805; Manufacturer: Panasonic; CompType: Resistor; Value: 0.1; Value_Code: R100; Tolerance_%: 1; Power_W: 0.125; Value2: 0.125W; TempCo: 250 ppm/C; EIA_Code: E96; U/M: EA
R43 = CRCW0402560RJNED: as R13 on sheet Power
R45 = CRCW04021K20JNED: RES, 1.2 k, 5%, 0.063 W, 0402; Manufacturer: Vishay-Dale; CompType: Resistor; Value: 1.2k; Res_ohm: 1200; Value_Code: 1k20; Tolerance_%: 5; Power_W: 0.063; Value2: 0.063W; VDC_V: 50; TempCo: 200 ppm/C; EIA_Code: E24; U/M: EA
R46 = CRCW04021K15FKED: RES, 1.15 k, 1%, 0.063 W, 0402; Manufacturer: Vishay-Dale; CompType: Resistor; Value: 1.15k; Res_ohm: 1150; Value_Code: 1k15; Tolerance_%: 1; Power_W: 0.063; Value2: 0.063W; VDC_V: 50; TempCo: 100 ppm/C; EIA_Code: E96; U/M: EA
R47 = CRCW0402510RJNED: RES, 510, 5%, 0.063 W, 0402; Manufacturer: Vishay-Dale; CompType: Resistor; Value: 510; Value_Code: 510R; Tolerance_%: 5; Power_W: 0.063; Value2: 0.063W; VDC_V: 50; TempCo: 200 ppm/C; EIA_Code: E24; U/M: EA
R49 = CRCW040210K0JNED: RES, 10 k, 5%, 0.063 W, 0402; Manufacturer: Vishay-Dale; CompType: Resistor; Value: 10k; Res_ohm: 10000; Value_Code: 10k0; Tolerance_%: 5; Power_W: 0.063; Value2: 0.063W; VDC_V: 50; TempCo: 200 ppm/C; EIA_Code: E24; U/M: EA
R50 R55 = CRCW04026K34FKED: RES, 6.34 k, 1%, 0.063 W, 0402; Manufacturer: Vishay-Dale; CompType: Resistor; Value: 6.34k; Res_ohm: 6340; Value_Code: 6k34; Tolerance_%: 1; Power_W: 0.063; Value2: 0.063W; VDC_V: 50; TempCo: 100 ppm/C; EIA_Code: E96; U/M: EA
R51 = CRCW04024K70JNED: RES, 4.7 k, 5%, 0.063 W, 0402; Manufacturer: Vishay-Dale; CompType: Resistor; Value: 4.7k; Res_ohm: 4700; Value_Code: 4k70; Tolerance_%: 5; Power_W: 0.063; Value2: 0.063W; VDC_V: 50; TempCo: 200 ppm/C; EIA_Code: E24; U/M: EA
R53 = CRCW040220K0JNED: RES, 20 k, 5%, 0.063 W, 0402; Manufacturer: Vishay-Dale; CompType: Resistor; Value: 20k; Res_ohm: 20000; Value_Code: 20k0; Tolerance_%: 5; Power_W: 0.063; Value2: 0.063W; VDC_V: 50; TempCo: 200 ppm/C; EIA_Code: E24; U/M: EA
R54 R59 = CRCW040249K9FKED: as R23 on sheet Power
R57 = CRCW0402309KFKED: RES, 309 k, 1%, 0.063 W, 0402; Manufacturer: Vishay-Dale; CompType: Resistor; Value: 309k; Res_ohm: 309000; Tolerance_%: 1; Power_W: 0.063; Value2: 0.063W; VDC_V: 50; TempCo: 100 ppm/C; EIA_Code: E96; U/M: EA
R60 = CRCW040223K7FKED: RES, 23.7 k, 1%, 0.063 W, 0402; Manufacturer: Vishay-Dale; CompType: Resistor; Value: 23.7k; Res_ohm: 23700; Value_Code: 23k7; Tolerance_%: 1; Power_W: 0.063; Value2: 0.063W; VDC_V: 50; TempCo: 100 ppm/C; EIA_Code: E96; U/M: EA
R86 = CRCW04028K06FKED: RES, 8.06 k, 1%, 0.063 W, 0402; Manufacturer: Vishay-Dale; CompType: Resistor; Value: 8.06k; Res_ohm: 8060; Value_Code: 8k06; Tolerance_%: 1; Power_W: 0.063; Value2: 0.063W; VDC_V: 50; TempCo: 100 ppm/C; EIA_Code: E96; U/M: EA
U4 = TPS24750RUV: 2.5 to 18 V Positive Voltage 10A Integrated Hot-Swap Controller, RUV0036A; Manufacturer: Texas Instruments; SymbolCreator: a0411947; CompType: IC; U/M: EA
U5 = LM2903D: Dual Comparator, D0008A; Manufacturer: Texas Instruments; CompType: OpAmp IC

## Sheet Host_Interface_MUX.SchDoc
size 431 x 279 mm; Date: Not shown in title block; ApprovedBy: Not shown in title block; CheckedBy: Not shown in title block; Author: Not shown in title block; CompanyName: Not shown in title block; Engineer: Not shown in title block; Organization: Not shown in title block; Address1: Not shown in title block; Address2: Not shown in title block; Address3: Not shown in title block; Address4: Not shown in title block; DocumentNumber: 1; Revision: Use project parameter SCH_Rev; SheetNumber: 2; SheetTotal: 3
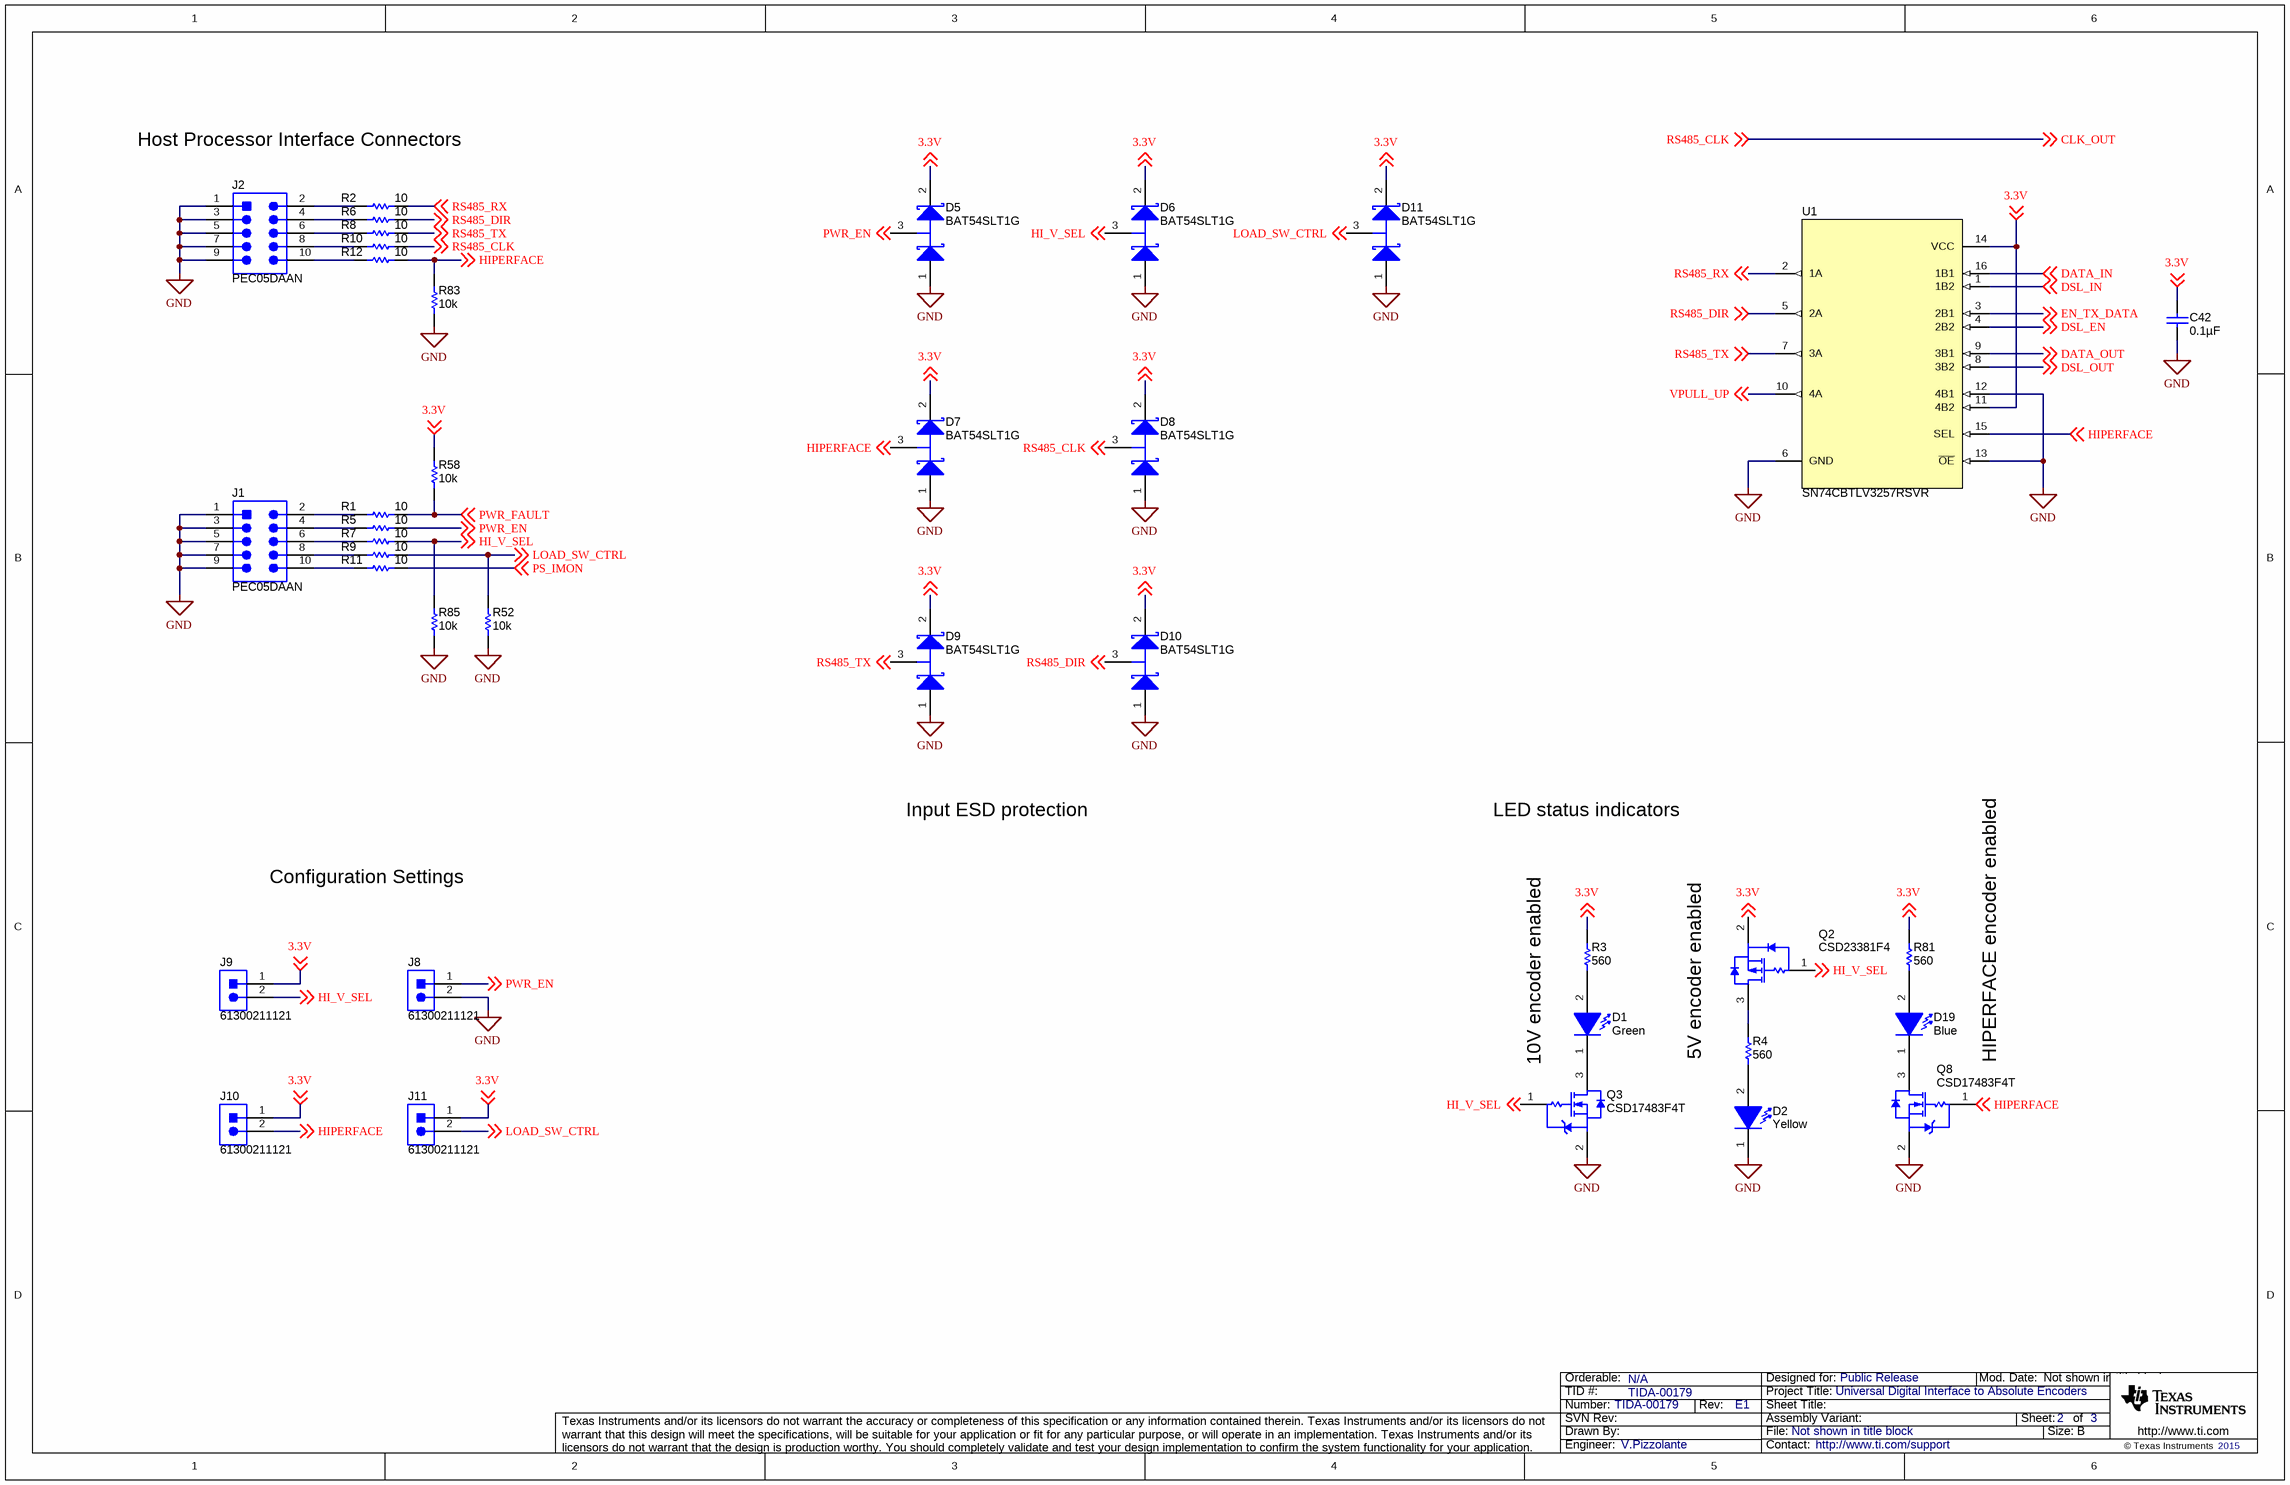
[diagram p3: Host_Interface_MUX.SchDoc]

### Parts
C42  ValueDisplayed: 0.1µF  [0603_095]  (hidden comment: 885012206046)
D1  value Green  [WL-SMCW_GREEN]  (hidden comment: 150060GS75000)
D2  value Yellow  [WL-SMCW_YELLOW]  (hidden comment: 150060YS75000)
D5  BAT54SLT1G  [SOT-23]
D6  BAT54SLT1G  [SOT-23]
D7  BAT54SLT1G  [SOT-23]
D8  BAT54SLT1G  [SOT-23]
D9  BAT54SLT1G  [SOT-23]
D10  BAT54SLT1G  [SOT-23]
D11  BAT54SLT1G  [SOT-23]
D19  value Blue  [WL-SMCW_Blue]  (hidden comment: 150060BS75000)
J1  PEC05DAAN  [CONN_PEC05DAAN]
J2  PEC05DAAN  [CONN_PEC05DAAN]
J8  61300211121  [WURTH_61300211121]
J9  61300211121  [WURTH_61300211121]
J10  61300211121  [WURTH_61300211121]
J11  61300211121  [WURTH_61300211121]
Q2  CSD23381F4  [YJC0003A]
Q3  CSD17483F4T  [YJC0003A]
Q8  CSD17483F4T  [YJC0003A]
R1  value 10  [0603]  (hidden comment: CRCW060310R0JNEAHP)
R2  value 10  [0603]  (hidden comment: CRCW060310R0JNEAHP)
R3  ValueDisplayed: 560  [0402]  (hidden comment: CRCW0402560RJNED)
R4  ValueDisplayed: 560  [0402]  (hidden comment: CRCW0402560RJNED)
R5  value 10  [0603]  (hidden comment: CRCW060310R0JNEAHP)
R6  value 10  [0603]  (hidden comment: CRCW060310R0JNEAHP)
R7  value 10  [0603]  (hidden comment: CRCW060310R0JNEAHP)
R8  value 10  [0603]  (hidden comment: CRCW060310R0JNEAHP)
R9  value 10  [0603]  (hidden comment: CRCW060310R0JNEAHP)
R10  value 10  [0603]  (hidden comment: CRCW060310R0JNEAHP)
R11  value 10  [0603]  (hidden comment: CRCW060310R0JNEAHP)
R12  value 10  [0603]  (hidden comment: CRCW060310R0JNEAHP)
R52  ValueDisplayed: 10k  [0402]  (hidden comment: CRCW040210K0JNED)
R58  ValueDisplayed: 10k  [0603]  (hidden comment: CRCW060310K0JNEA)
R81  ValueDisplayed: 560  [0402]  (hidden comment: CRCW0402560RJNED)
R83  ValueDisplayed: 10k  [0402]  (hidden comment: CRCW040210K0JNED)
R85  ValueDisplayed: 10k  [0402]  (hidden comment: CRCW040210K0JNED)
U1  SN74CBTLV3257RSVR  [RSV0016A]

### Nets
GND: C42.1 D2.1(K) D5.1(A) D6.1(A) D7.1(A) D8.1(A) D9.1(A) D10.1(A) D11.1(A) J1.1 J1.3 J1.5 J1.7 J1.9 J2.1 J2.3 J2.5 J2.7 J2.9 J8.2 Q3.2(S) Q8.2(S) R52.1 R83.1 R85.1 U1.6(GND) U1.12(4B1) U1.13(~{OE})
3.3V: C42.2 D5.2(K) D6.2(K) D7.2(K) D8.2(K) D9.2(K) D10.2(K) D11.2(K) J9.1 J10.1 J11.1 Q2.2(S) R3.2 R58.2 R81.2 U1.11(4B2) U1.14(VCC) ; off-sheet 3.3V
CLK_OUT: D8.3(C) R10.2 ; off-sheet RS485_CLK, off-sheet CLK_OUT  [also labelled RS485_CLK]
DATA_IN: U1.16(1B1) ; off-sheet DATA_IN
DATA_OUT: U1.9(3B1) ; off-sheet DATA_OUT
DSL_EN: U1.4(2B2) ; off-sheet DSL_EN
DSL_IN: U1.1(1B2) ; off-sheet DSL_IN
DSL_OUT: U1.8(3B2) ; off-sheet DSL_OUT
EN_TX_DATA: U1.3(2B1) ; off-sheet EN_TX_DATA
HI_V_SEL: D6.3(C) J9.2 Q2.1(G) Q3.1(G) R7.2 R85.2 ; off-sheet HI_V_SEL
HIPERFACE: D7.3(C) J10.2 Q8.1(G) R12.2 R83.2 U1.15(SEL) ; off-sheet HIPERFACE
LOAD_SW_CTRL: D11.3(C) J11.2 R9.2 R52.2 ; off-sheet LOAD_SW_CTRL
PS_IMON: R11.2 ; off-sheet PS_IMON
PWR_EN: D5.3(C) J8.1 R5.2 ; off-sheet PWR_EN
PWR_FAULT: R1.2 R58.1 ; off-sheet PWR_FAULT
RS485_DIR: D10.3(C) R6.2 U1.5(2A) ; off-sheet RS485_DIR
RS485_RX: R2.2 U1.2(1A) ; off-sheet RS485_RX
RS485_TX: D9.3(C) R8.2 U1.7(3A) ; off-sheet RS485_TX
VPULL_UP: U1.10(4A) ; off-sheet VPULL_UP
NetD1_1: D1.1(K) Q3.3(D)
NetD1_2: D1.2(A) R3.1
NetD2_2: D2.2(A) R4.1
NetD19_1: D19.1(K) Q8.3(D)
NetD19_2: D19.2(A) R81.1
NetJ1_2: J1.2 R1.1
NetJ1_4: J1.4 R5.1
NetJ1_6: J1.6 R7.1
NetJ1_8: J1.8 R9.1
NetJ1_10: J1.10 R11.1
NetJ2_2: J2.2 R2.1
NetJ2_4: J2.4 R6.1
NetJ2_6: J2.6 R8.1
NetJ2_8: J2.8 R10.1
NetJ2_10: J2.10 R12.1
NetQ2_3: Q2.3(D) R4.2

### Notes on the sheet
- Host Processor Interface Connectors
- Input ESD protection
- LED status indicators
- Configuration Settings
- 10V encoder enabled
- 5V encoder enabled
- HIPERFACE encoder enabled

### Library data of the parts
C42 = 885012206046: as C25 on sheet Protections
D1 = 150060GS75000: as D17 on sheet Power
D2 = 150060YS75000: LED, Yellow, SMD; Manufacturer: Wurth Elektronik; Type: AlInGaP; Vf_V: 2; Value2: 2V; Io_A: 0.02; Value1: W; U/M: EA
D5-D11 = BAT54SLT1G: Diode, Schottky, 30 V, 0.2 A, SOT-23; Manufacturer: ON Semiconductor; U/M: EA; Vf_V: 0.8; Value: 30V; Value1: 0.2A; Value2: 0.8V; Io_A: 0.2; Vr_V: 30; TJmax_C: 150
D19 = 150060BS75000: LED, Blue, SMD; Manufacturer: Wurth Elektronik; Type: InGaN; Vf_V: 3.2; Value2: 3.2V; Io_A: 0.03; Vr_V: 5; Tjmax_C: 85; Power_TotalModule: 0.105; Value1: 0.105W; Angle: 140; U/M: EA
J1 J2 = PEC05DAAN: Header, 100mil, 5x2, Tin, TH; Manufacturer: Sullins Connector Solutions; SymbolCreator: a0412235; U/M: EA
J8-J11 = 61300211121: as J3 on sheet Power
Q2 = CSD23381F4: MOSFET, P-CH, -12 V, -2.3 A,; Manufacturer: Texas Instruments; Alternate Manufacturer: None; SymbolCreator: a0411947; U/M: EA; ChType: P; Value: -12V; Value1: 0.15 ohm; Rdson45_ohm: 0.15; Value2: 1.14 nC; QgTyp_nC: 1.14; Vgs_V: 8
Q3 Q8 = CSD17483F4T: as Q4 on sheet Power
R1 R2 R5-R12 = CRCW060310R0JNEAHP: RES, 10 ohm, 5%, 0.25W, 0603; Manufacturer: Vishay-Dale; CompType: Resistor; Value_Code: 10R0; Tolerance_%: 5; Power_W: 0.25; VDC_V: 75; TempCo: 200 ppm/C; EIA_Code: E24; U/M: EA
R3 R4 R81 = CRCW0402560RJNED: as R13 on sheet Power
R52 R83 R85 = CRCW040210K0JNED: as R49 on sheet Protections
R58 = CRCW060310K0JNEA: RES, 10 k, 5%, 0.1 W, 0603; Manufacturer: Vishay-Dale; CompType: Resistor; Res_ohm: 10000; Value: 10k; Value_Code: 10k0; Tolerance_%: 5; Power_W: 0.1; Value2: 0.1W; VDC_V: 75; TempCo: 200 ppm/C; EIA_Code: E24; U/M: EA
U1 = SN74CBTLV3257RSVR: Low-Voltage 4-Bit 1-of-2 FET Multiplexer/Demultiplexer, RSV0016A; Manufacturer: Texas Instruments; SymbolCreator: Altium; CompType: IC; U/M: EA

## Sheet RS485.SchDoc
size 431 x 279 mm; Date: Not shown in title block; ApprovedBy: Not shown in title block; CheckedBy: Not shown in title block; Author: Not shown in title block; CompanyName: Not shown in title block; Engineer: Not shown in title block; Organization: Not shown in title block; Address1: Not shown in title block; Address2: Not shown in title block; Address3: Not shown in title block; Address4: Not shown in title block; DocumentNumber: 1; Revision: Use project parameter SCH_Rev; SheetNumber: 2; SheetTotal: 3
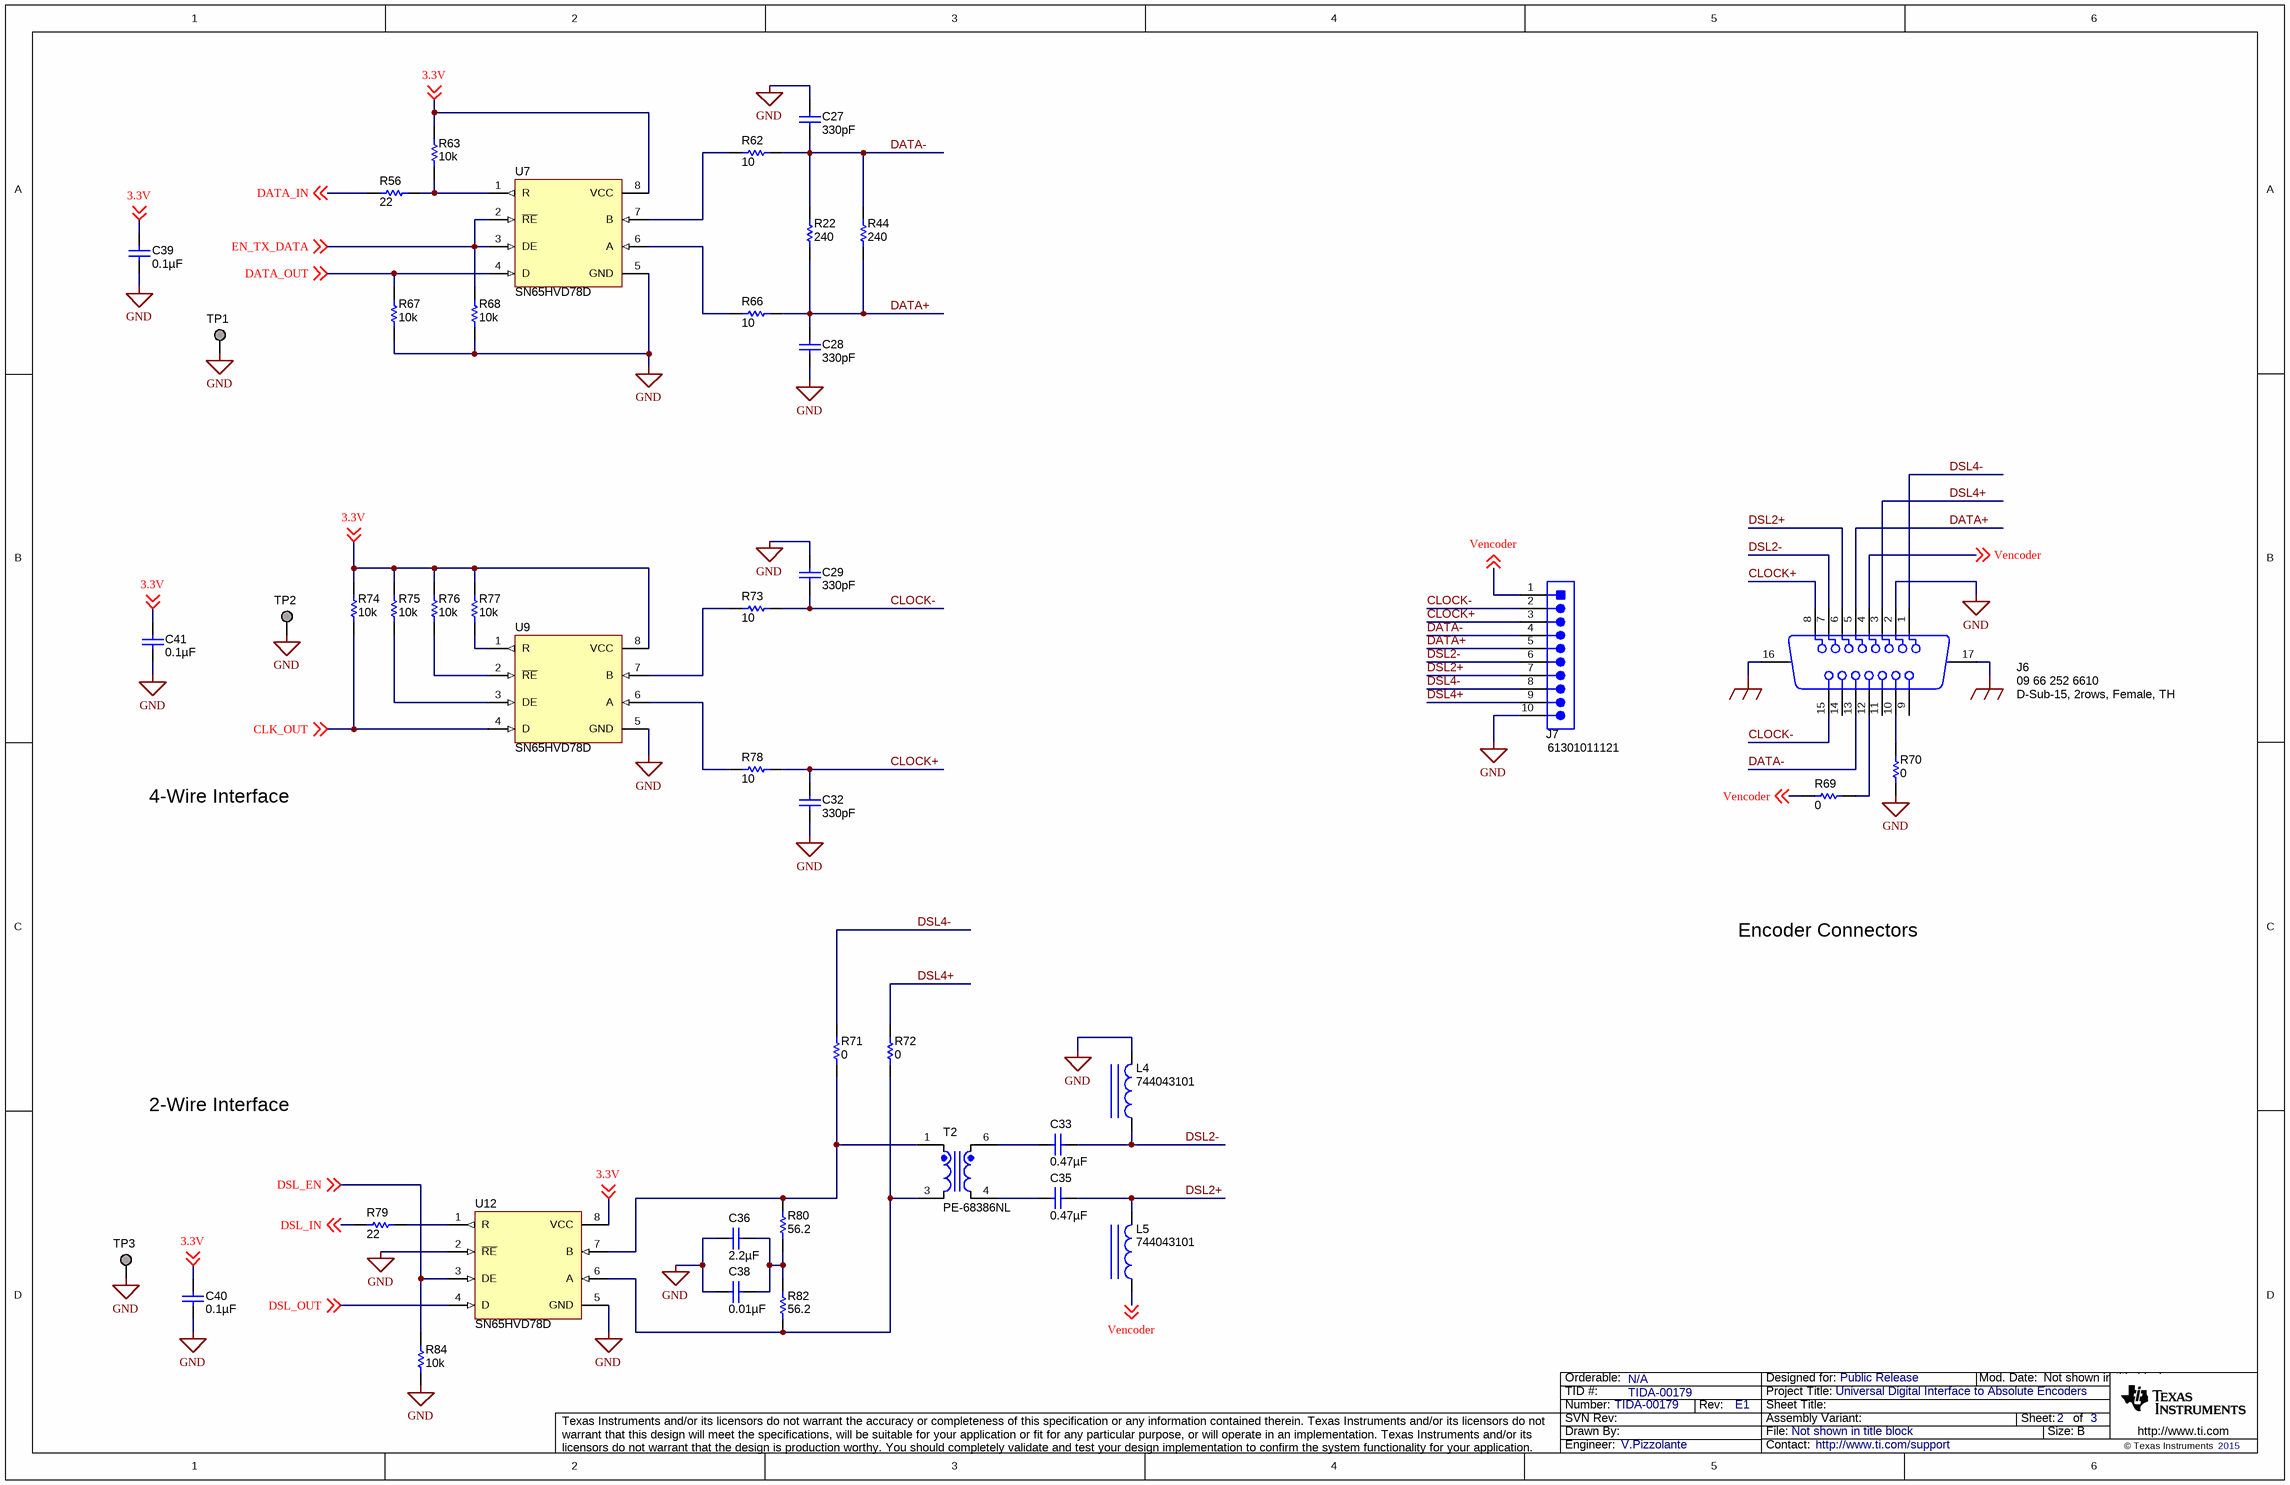
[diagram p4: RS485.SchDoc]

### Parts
C27  ValueDisplayed: 330pF  [0603]  (hidden comment: 885012006060)
C28  ValueDisplayed: 330pF  [0603]  (hidden comment: 885012006060)
C29  ValueDisplayed: 330pF  [0603]  (hidden comment: 885012006060)
C32  ValueDisplayed: 330pF  [0603]  (hidden comment: 885012006060)
C33  ValueDisplayed: 0.47µF  [0805_HV]  (hidden comment: 885012207102)
C35  ValueDisplayed: 0.47µF  [0805_HV]  (hidden comment: 885012207102)
C36  ValueDisplayed: 2.2µF  [0805_HV]  (hidden comment: GRM21BR71E225KA73L)
C38  ValueDisplayed: 0.01µF  [0805_HV]  (hidden comment: GRM2195C1H103JA01D)
C39  ValueDisplayed: 0.1µF  [0603_095]  (hidden comment: 885012206046)
C40  ValueDisplayed: 0.1µF  [0603_095]  (hidden comment: 885012206046)
C41  ValueDisplayed: 0.1µF  [0603_095]  (hidden comment: 885012206046)
J6  09 66 252 6610  PackageReference: D-Sub-15, 2rows, Female, TH  [Harting_09 66 252 6610]
J7  61301011121  [Wurth_61301011121]
L4  744043101  [WE-TPC_4828]
L5  744043101  [WE-TPC_4828]
R22  ValueDisplayed: 240  [0603]  (hidden comment: CRCW0603240RJNEA)
R44  ValueDisplayed: 240  [0603]  (hidden comment: CRCW0603240RJNEA)
R56  ValueDisplayed: 22  [0402]  (hidden comment: CRCW040222R0JNED)
R62  value 10  [0603]  (hidden comment: CRCW060310R0JNEAHP)
R63  ValueDisplayed: 10k  [0402]  (hidden comment: CRCW040210K0JNED)
R66  value 10  [0603]  (hidden comment: CRCW060310R0JNEAHP)
R67  ValueDisplayed: 10k  [0402]  (hidden comment: CRCW040210K0JNED)
R68  ValueDisplayed: 10k  [0402]  (hidden comment: CRCW040210K0JNED)
R69  ValueDisplayed: 0  [0402]  (hidden comment: CRCW04020000Z0ED)
R70  ValueDisplayed: 0  [0402]  (hidden comment: CRCW04020000Z0ED)
R71  ValueDisplayed: 0  [0402]  (hidden comment: CRCW04020000Z0ED)
R72  ValueDisplayed: 0  [0402]  (hidden comment: CRCW04020000Z0ED)
R73  value 10  [0603]  (hidden comment: CRCW060310R0JNEAHP)
R74  ValueDisplayed: 10k  [0402]  (hidden comment: CRCW040210K0JNED)
R75  ValueDisplayed: 10k  [0402]  (hidden comment: CRCW040210K0JNED)
R76  ValueDisplayed: 10k  [0402]  (hidden comment: CRCW040210K0JNED)
R77  ValueDisplayed: 10k  [0402]  (hidden comment: CRCW040210K0JNED)
R78  value 10  [0603]  (hidden comment: CRCW060310R0JNEAHP)
R79  ValueDisplayed: 22  [0402]  (hidden comment: CRCW040222R0JNED)
R80  ValueDisplayed: 56.2  [0805_HV]  (hidden comment: CRCW080556R2FKEA)
R82  ValueDisplayed: 56.2  [0805_HV]  (hidden comment: CRCW080556R2FKEA)
R84  ValueDisplayed: 10k  [0402]  (hidden comment: CRCW040210K0JNED)
T2  PE-68386NL  [PULSE_PE-68386NL]
TP1  TESTPOINT  [OXLEY_SMOX_060_B1_LP]  (value not drawn)  (no BOM)
TP2  TESTPOINT  [OXLEY_SMOX_060_B1_LP]  (value not drawn)  (no BOM)
TP3  TESTPOINT  [OXLEY_SMOX_060_B1_LP]  (value not drawn)  (no BOM)
U7  SN65HVD78D  [D0008A_N]
U9  SN65HVD78D  [D0008A_N]
U12  SN65HVD78D  [D0008A_N]

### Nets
GND: C27.1 C28.2 C29.1 C32.2 C36.2 C38.2 C39.1 C40.1 C41.1 J6.2 J7.10 L4.2 R67.1 R68.1 R70.1 R84.1 TP1.1 TP2.1 TP3.1 U7.5(GND) U9.5(GND) U12.2(~{RE}) U12.5(GND)
NetJ6_16: J6.16(MH1) J6.17(MH2)
3.3V: C39.2 C40.2 C41.2 R63.2 R74.2 R75.2 R76.2 R77.2 U7.8(VCC) U9.8(VCC) U12.8(VCC) ; off-sheet 3.3V
CLK_OUT: R74.1 U9.4(D) ; off-sheet CLK_OUT
CLOCK+: C32.1 J6.8 J7.3 R78.2
CLOCK-: C29.2 J6.15 J7.2 R73.2
DATA+: C28.1 J6.5 J7.5 R22.1 R44.1 R66.2
DATA-: C27.2 J6.13 J7.4 R22.2 R44.2 R62.2
DATA_IN: R56.1 ; off-sheet DATA_IN
DATA_OUT: R67.2 U7.4(D) ; off-sheet DATA_OUT
DSL2+: C35.1 J6.6 J7.7 L5.2
DSL2-: C33.1 J6.7 J7.6 L4.1
DSL4+: J6.3 J7.9 R72.2
DSL4-: J6.1 J7.8 R71.2
DSL_EN: R84.2 U12.3(DE) ; off-sheet DSL_EN
DSL_IN: R79.1 ; off-sheet DSL_IN
DSL_OUT: U12.4(D) ; off-sheet DSL_OUT
EN_TX_DATA: R68.2 U7.2(~{RE}) U7.3(DE) ; off-sheet EN_TX_DATA
Vencoder: J6.4 J7.1 L5.1 R69.1 ; off-sheet Vencoder
NetC33_2: C33.2 T2.6
NetC35_2: C35.2 T2.4
NetC36_1: C36.1 C38.1 R80.1 R82.2
NetJ6_10: J6.10 R70.2
NetJ6_12: J6.12 R69.2
NetR56_2: R56.2 R63.1 U7.1(R)
NetR62_1: R62.1 U7.7(B)
NetR66_1: R66.1 U7.6(A)
NetR71_1: R71.1 R80.2 T2.1 U12.7(B)
NetR72_1: R72.1 R82.1 T2.3 U12.6(A)
NetR73_1: R73.1 U9.7(B)
NetR75_1: R75.1 U9.3(DE)
NetR76_1: R76.1 U9.2(~{RE})
NetR77_1: R77.1 U9.1(R)
NetR78_1: R78.1 U9.6(A)
NetR79_2: R79.2 U12.1(R)

Not connected (* = marked no-connect by the designer): J6 9 11 14

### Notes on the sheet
- 4-Wire Interface
- Encoder Connectors
- 2-Wire Interface

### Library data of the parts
C27-C29 C32 = 885012006060: CAP, CERM, 330 pF, 50 V, +/- 5%, C0G/NP0, 0603; Manufacturer: Wurth Elektronik; Polarized: N; CompType: Capacitor; Value: 330pF; U/M: EA; Cap_F: 0.00000000033; Tolerance_%: 5; Value1: Unknown; VDC_V: 50; Value2: 50V; TaMin_C: -55; TaMax_C: 125
C33 C35 = 885012207102: CAP, CERM, 0.47 µF, 50 V, +/- 10%, X7R, 0805; Manufacturer: Wurth Elektronik; Polarized: N; CompType: Capacitor; Value: 0.47uF; U/M: EA; Cap_F: 0.00000047; Tolerance_%: 10; Value1: Unknown; VDC_V: 50; Value2: 50V; TaMin_C: -55; TaMax_C: 125; Cap_Case: 0805
C36 = GRM21BR71E225KA73L: CAP, CERM, 2.2 µF, 25 V, +/- 10%, X7R, 0805; Manufacturer: MuRata; Polarized: N; CompType: Capacitor; Value: 2.2uF; U/M: EA; Cap_F: 0.0000022; Tolerance_%: 10; ESR_ohm: 0.005; Value1: 0.005 ohm; VDC_V: 25; Value2: 25V; TaMin_C: -55; TaMax_C: 125; Cap_Case: 0805
C38 = GRM2195C1H103JA01D: CAP, CERM, 0.01 µF, 50 V, +/- 5%, C0G/NP0, 0805; Manufacturer: MuRata; Polarized: N; CompType: Capacitor; Value: 0.01uF; U/M: EA; Cap_F: 0.00000001; Tolerance_%: 5; Value1: Unknown; VDC_V: 50; Value2: 50V; TaMin_C: -55; TaMax_C: 125; Cap_Case: 0805
C39-C41 = 885012206046: as C25 on sheet Protections
J6 = 09 66 252 6610: D-Sub-15, 17Pos, TH; Manufacturer: Harting; SymbolCreator: x0208325; CompType: D-Sub; U/M: EA
J7 = 61301011121: Header, 2.54mm, 10x1, Gold, TH; Manufacturer: Wurth Elektronik; SymbolCreator: a0412235; U/M: EA
L4 L5 = 744043101: Inductor, Shielded Drum Core, Ferrite, 100 µH, 0.3 A, 0.52 ohm, SMD; Manufacturer: Wurth Elektronik; Value: 100uH; Ind_H: 100.0E-6; ValueDisplayed: 100µH; Imax_A: 0.3; Irms: 0.51A @ 30C rise; Isat: 0.3A @ 35% inductance drop; DCR_ohm: 0.52; Value2: 0.3A
R22 R44 = CRCW0603240RJNEA: RES, 240, 5%, 0.1 W, 0603; Manufacturer: Vishay-Dale; CompType: Resistor; Value: 240; Value_Code: 240R; Tolerance_%: 5; Power_W: 0.1; Value2: 0.1W; VDC_V: 75; TempCo: 200 ppm/C; EIA_Code: E24; U/M: EA
R56 R79 = CRCW040222R0JNED: RES, 22, 5%, 0.063 W, 0402; Manufacturer: Vishay-Dale; CompType: Resistor; Value: 22; Value_Code: 22R0; Tolerance_%: 5; Power_W: 0.063; Value2: 0.063W; VDC_V: 50; TempCo: 200 ppm/C; EIA_Code: E24; U/M: EA
R62 R66 R73 R78 = CRCW060310R0JNEAHP: as R1 on sheet Host_Interface_MUX
R63 R67 R68 R74-R77 R84 = CRCW040210K0JNED: as R49 on sheet Protections
R69-R72 = CRCW04020000Z0ED: as R18 on sheet Power
R80 R82 = CRCW080556R2FKEA: RES, 56.2, 1%, 0.125 W, 0805; Manufacturer: Vishay-Dale; CompType: Resistor; Value: 56.2; Value_Code: 56R2; Tolerance_%: 1; Power_W: 0.125; Value2: 0.125W; VDC_V: 150; TempCo: 100 ppm/C; EIA_Code: E96; U/M: EA
T2 = PE-68386NL: Transformers, Gate Drive , 785uH, SMT; Manufacturer: Pulse Engineering; SymbolCreator: a0799628; DCR_Ohm: 0.6; LeakageL: 0.46 uH; U/M: EA
TP1-TP3 = SMOX/060/B1LP.R3K: Test Point, Silver, SMD; Manufacturer: Oxley; U/M: EA
U7 U9 = SN65HVD78D: 3.3V-Supply RS-485 with IEC ESD Protection, D0008A; Alternate Manufacturer: None; Manufacturer: Texas Instruments; SymbolCreator: a0411947; CompType: IC; U/M: EA
U12 = SN65HVD78D: 3.3V-Supply RS-485 with IEC ESD Protection, D0008A; Manufacturer: Texas Instruments; SymbolCreator: a0411947; CompType: IC; U/M: EA

## Sheet TID_Hardware.SchDoc
size 431 x 279 mm; Date: Not shown in title block; ApprovedBy: Not shown in title block; CheckedBy: Not shown in title block; Author: Not shown in title block; CompanyName: Not shown in title block; Engineer: Not shown in title block; Organization: Not shown in title block; Address1: Not shown in title block; Address2: Not shown in title block; Address3: Not shown in title block; Address4: Not shown in title block; DocumentNumber: 1; Revision: Use project parameter SCH_Rev; SheetNumber: 3; SheetTotal: 3; PageSetup: Record=PageOptions¦CenterHorizontal=True¦CenterVertical=True¦PrintScale=1.00¦XCorrection=1.00¦YCorrection=1.00¦PrintKind=0¦BorderSize=5000000¦LeftOffset=0¦BottomOffset=0¦Orientation=2¦PaperLength=1000¦PaperWidth=1000¦Scale=100¦PaperSource=15¦PrintQuality=600¦MediaType=1¦DitherType=10¦PaperKind=Letter¦PrintScaleMode=1
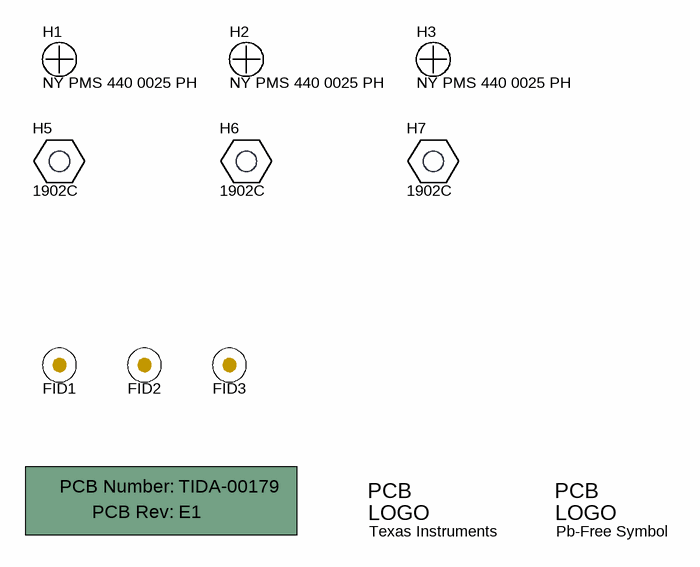
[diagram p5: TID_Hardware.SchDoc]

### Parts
!PCB1  Printed Circuit Board  (value not drawn)  (mechanical)
FID1  Fiducial  [Fiducial10-20]  (value not drawn)
FID2  Fiducial  [Fiducial10-20]  (value not drawn)
FID3  Fiducial  [Fiducial10-20]  (value not drawn)
H1  NY PMS 440 0025 PH  [NY PMS 440 0025 PH]
H2  NY PMS 440 0025 PH  [NY PMS 440 0025 PH]
H3  NY PMS 440 0025 PH  [NY PMS 440 0025 PH]
H5  1902C  [Keystone_1902C]
H6  1902C  [Keystone_1902C]
H7  1902C  [Keystone_1902C]
Logo1  Texas Instruments  [TI_Stacked_SolderMask_Small]  (no BOM)
Logo2  Pb-Free Symbol  [Pb-Free_Overlay_Small]  (no BOM)

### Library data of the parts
!PCB1 = PCB: Manufacturer: Any; PartNumber: TIDA-00179; SymbolCreator: a0412235
FID1-FID3 = Fiducial: Fiducial mark.  There is nothing to buy or mount.; SymbolCreator: codlsc
H1-H3 = NY PMS 440 0025 PH: Machine Screw, Round, #4-40 x 1/4, Nylon, Philips panhead; Manufacturer: B&F Fastener Supply; CompType: Hardware; SymbolCreator: codlsc; U/M: EA
H5-H7 = 1902C: Standoff, Hex, 0.5"L #4-40 Nylon; Manufacturer: Keystone; CompType: Hardware
Logo1 = TI_Logo: Texas Instrument Corporate Signature; SymbolCreator: codlsc
Logo2 = Pb-Free: SymbolCreator: a0412235

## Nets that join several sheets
GND: Power (37 pins), Protections (28 pins), Host_Interface_MUX (28 pins), RS485 (23 pins)
3.3V: Power (5 pins), Protections (C26.2 R43.2 R51.2 U5.8), Host_Interface_MUX (17 pins), RS485 (11 pins)
CLK_OUT: Host_Interface_MUX (D8.3 R10.2), RS485 (R74.1 U9.4)
DATA_IN: Host_Interface_MUX (U1.16), RS485 (R56.1)
DATA_OUT: Host_Interface_MUX (U1.9), RS485 (R67.2 U7.4)
DSL_EN: Host_Interface_MUX (U1.4), RS485 (R84.2 U12.3)
DSL_IN: Host_Interface_MUX (U1.1), RS485 (R79.1)
DSL_OUT: Host_Interface_MUX (U1.8), RS485 (U12.4)
EN_TX_DATA: Host_Interface_MUX (U1.3), RS485 (R68.2 U7.2 U7.3)
HI_V_SEL: Power (Q4.1), Protections (Q1.1), Host_Interface_MUX (6 pins)
LOAD_SW_CTRL: Protections (Q7.1), Host_Interface_MUX (D11.3 J11.2 R9.2 R52.2)
PS_IMON: Protections (R46.2 U4.2), Host_Interface_MUX (R11.2)
PWR_EN: Power (R15.2), Host_Interface_MUX (D5.3 J8.1 R5.2)
PWR_FAULT: Protections (U4.30), Host_Interface_MUX (R1.2 R58.1)
Vencoder: Protections (C21.1 Q5.1 Q5.2 Q5.3), RS485 (J6.4 J7.1 L5.1 R69.1)
Vout: Power (R17.2), Protections (6 pins)
VPULL_UP: Protections (C31.2 R50.2), Host_Interface_MUX (U1.10)

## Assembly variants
First Assembly: not fitted FID1 FID2 FID3
Production: not fitted D16 R25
